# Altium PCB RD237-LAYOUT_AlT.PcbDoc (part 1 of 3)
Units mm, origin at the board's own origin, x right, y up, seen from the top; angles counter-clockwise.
Board outline 100 x 82 mm, 4 copper layers (Top Layer, GND2, POWER 3, Bottom Layer), stack 1.444 mm thick; 308 components, 134 nets, 738 pads, 304 vias.
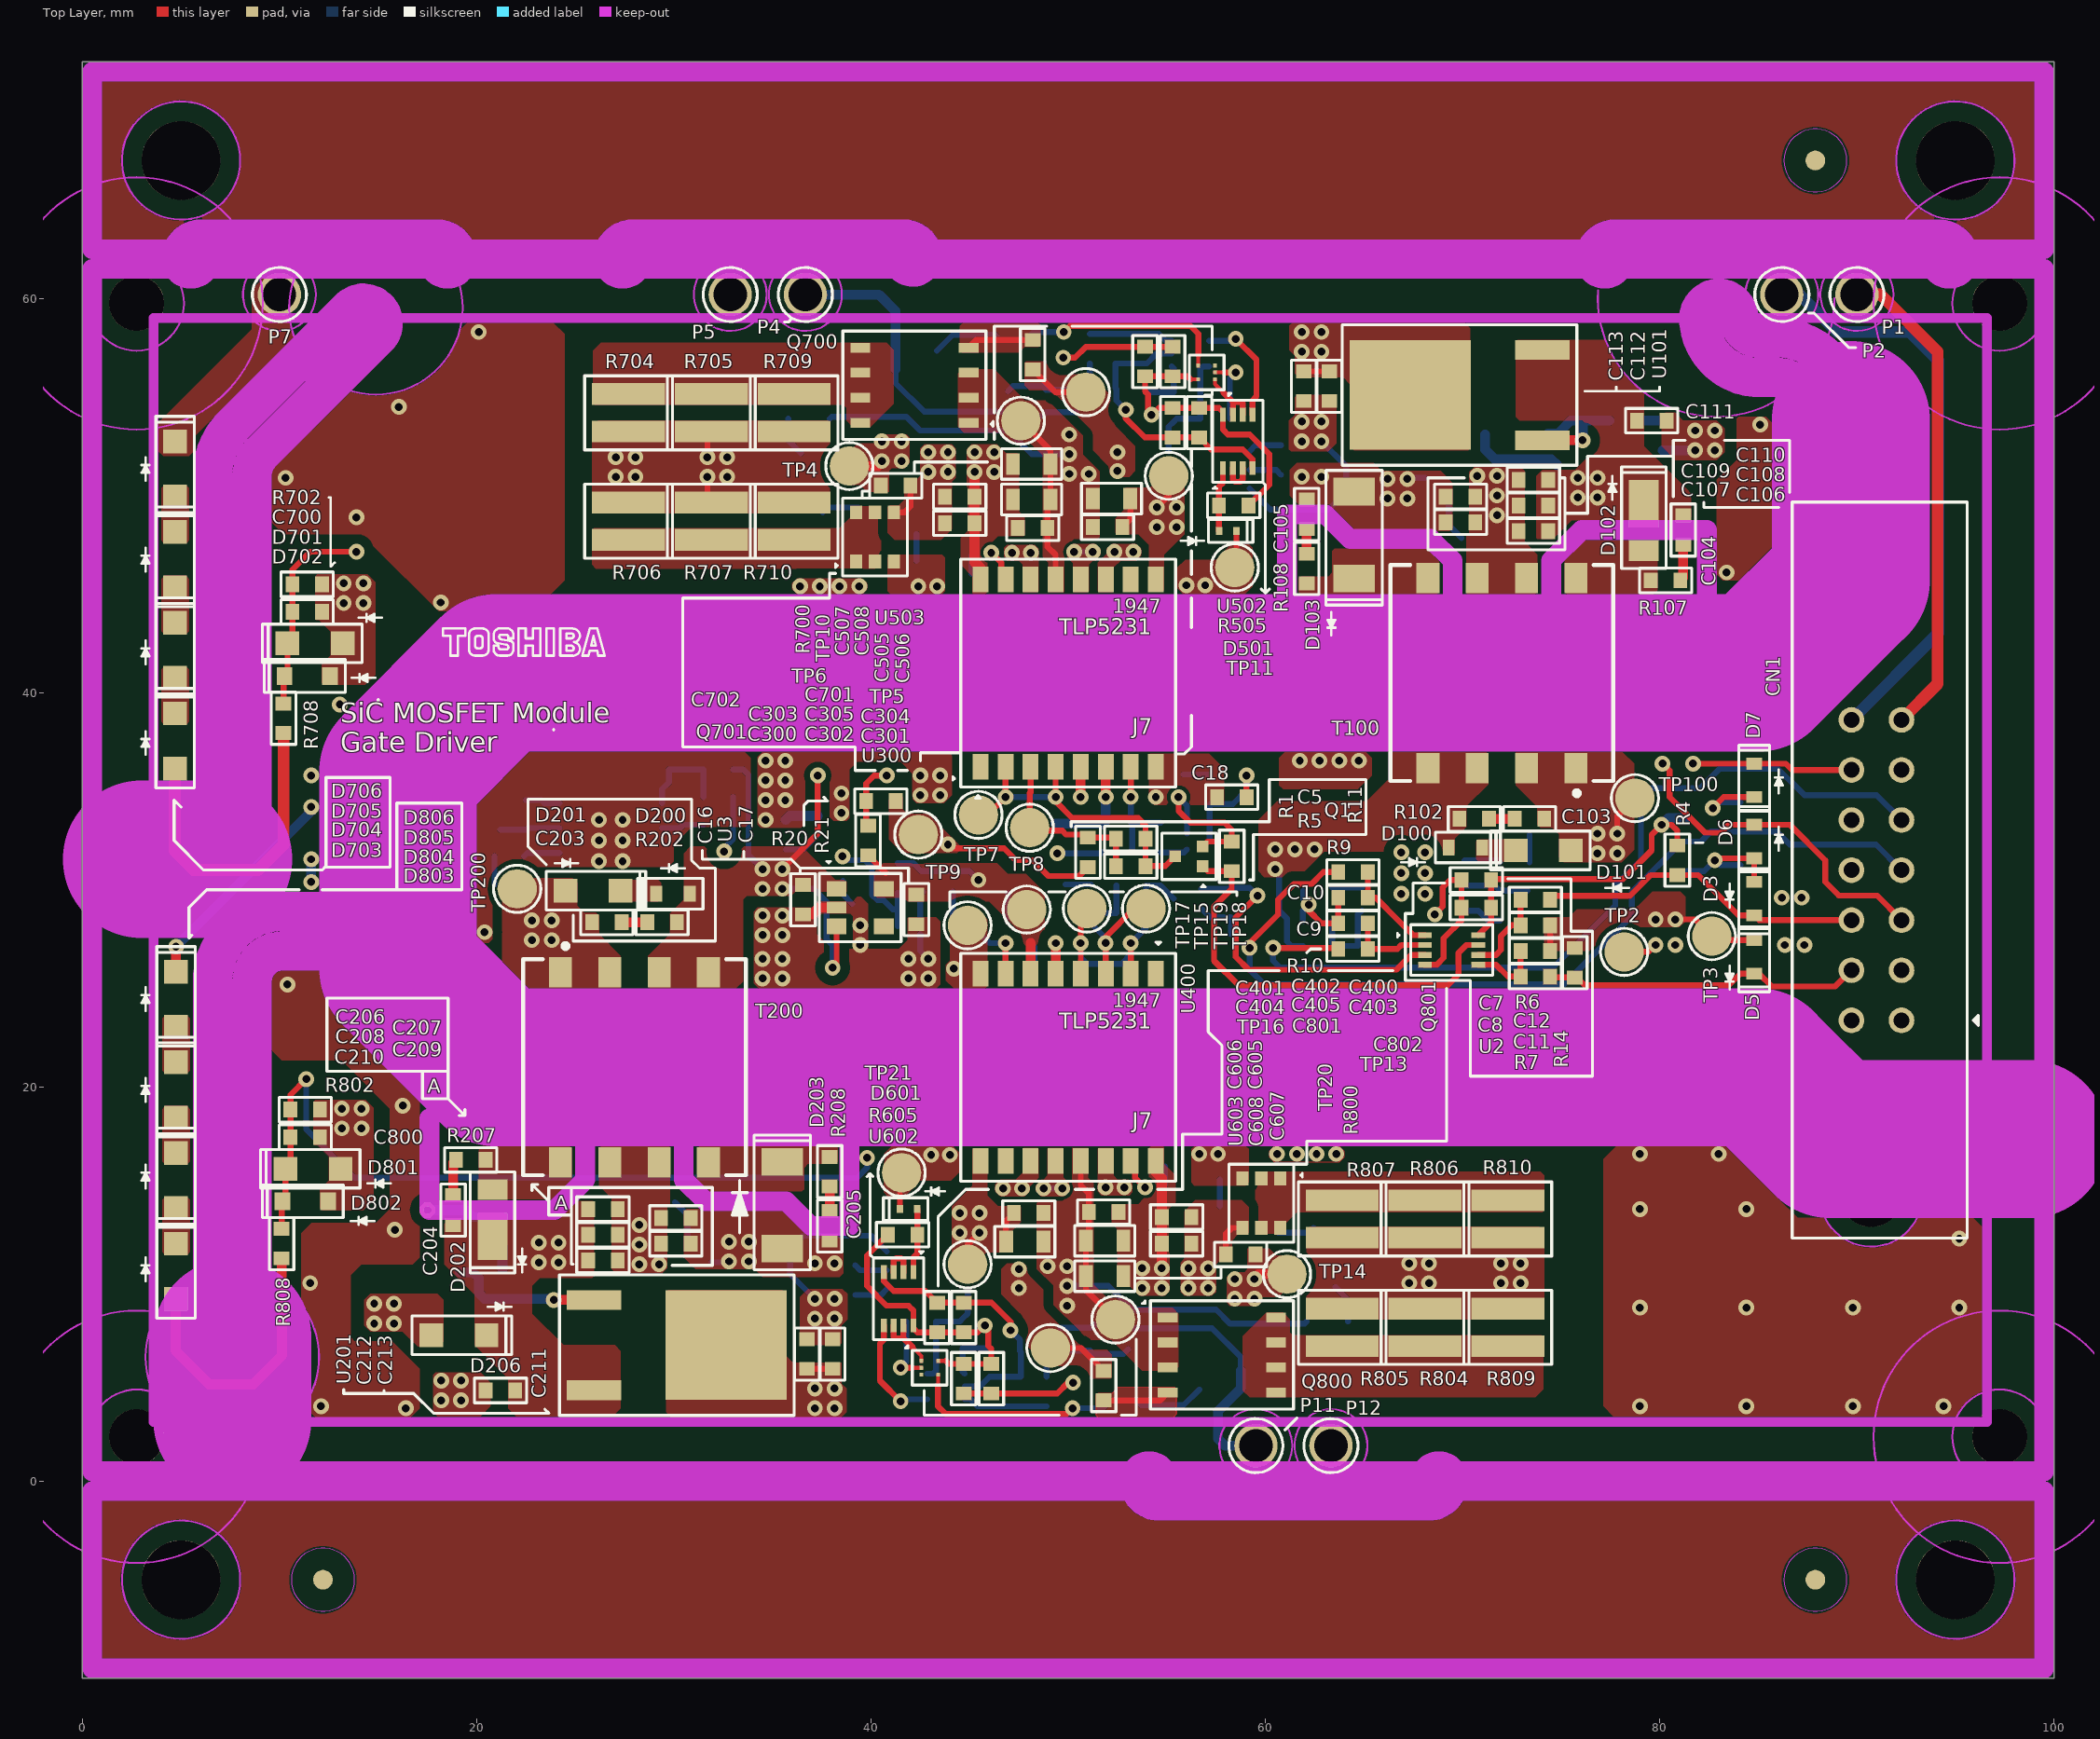
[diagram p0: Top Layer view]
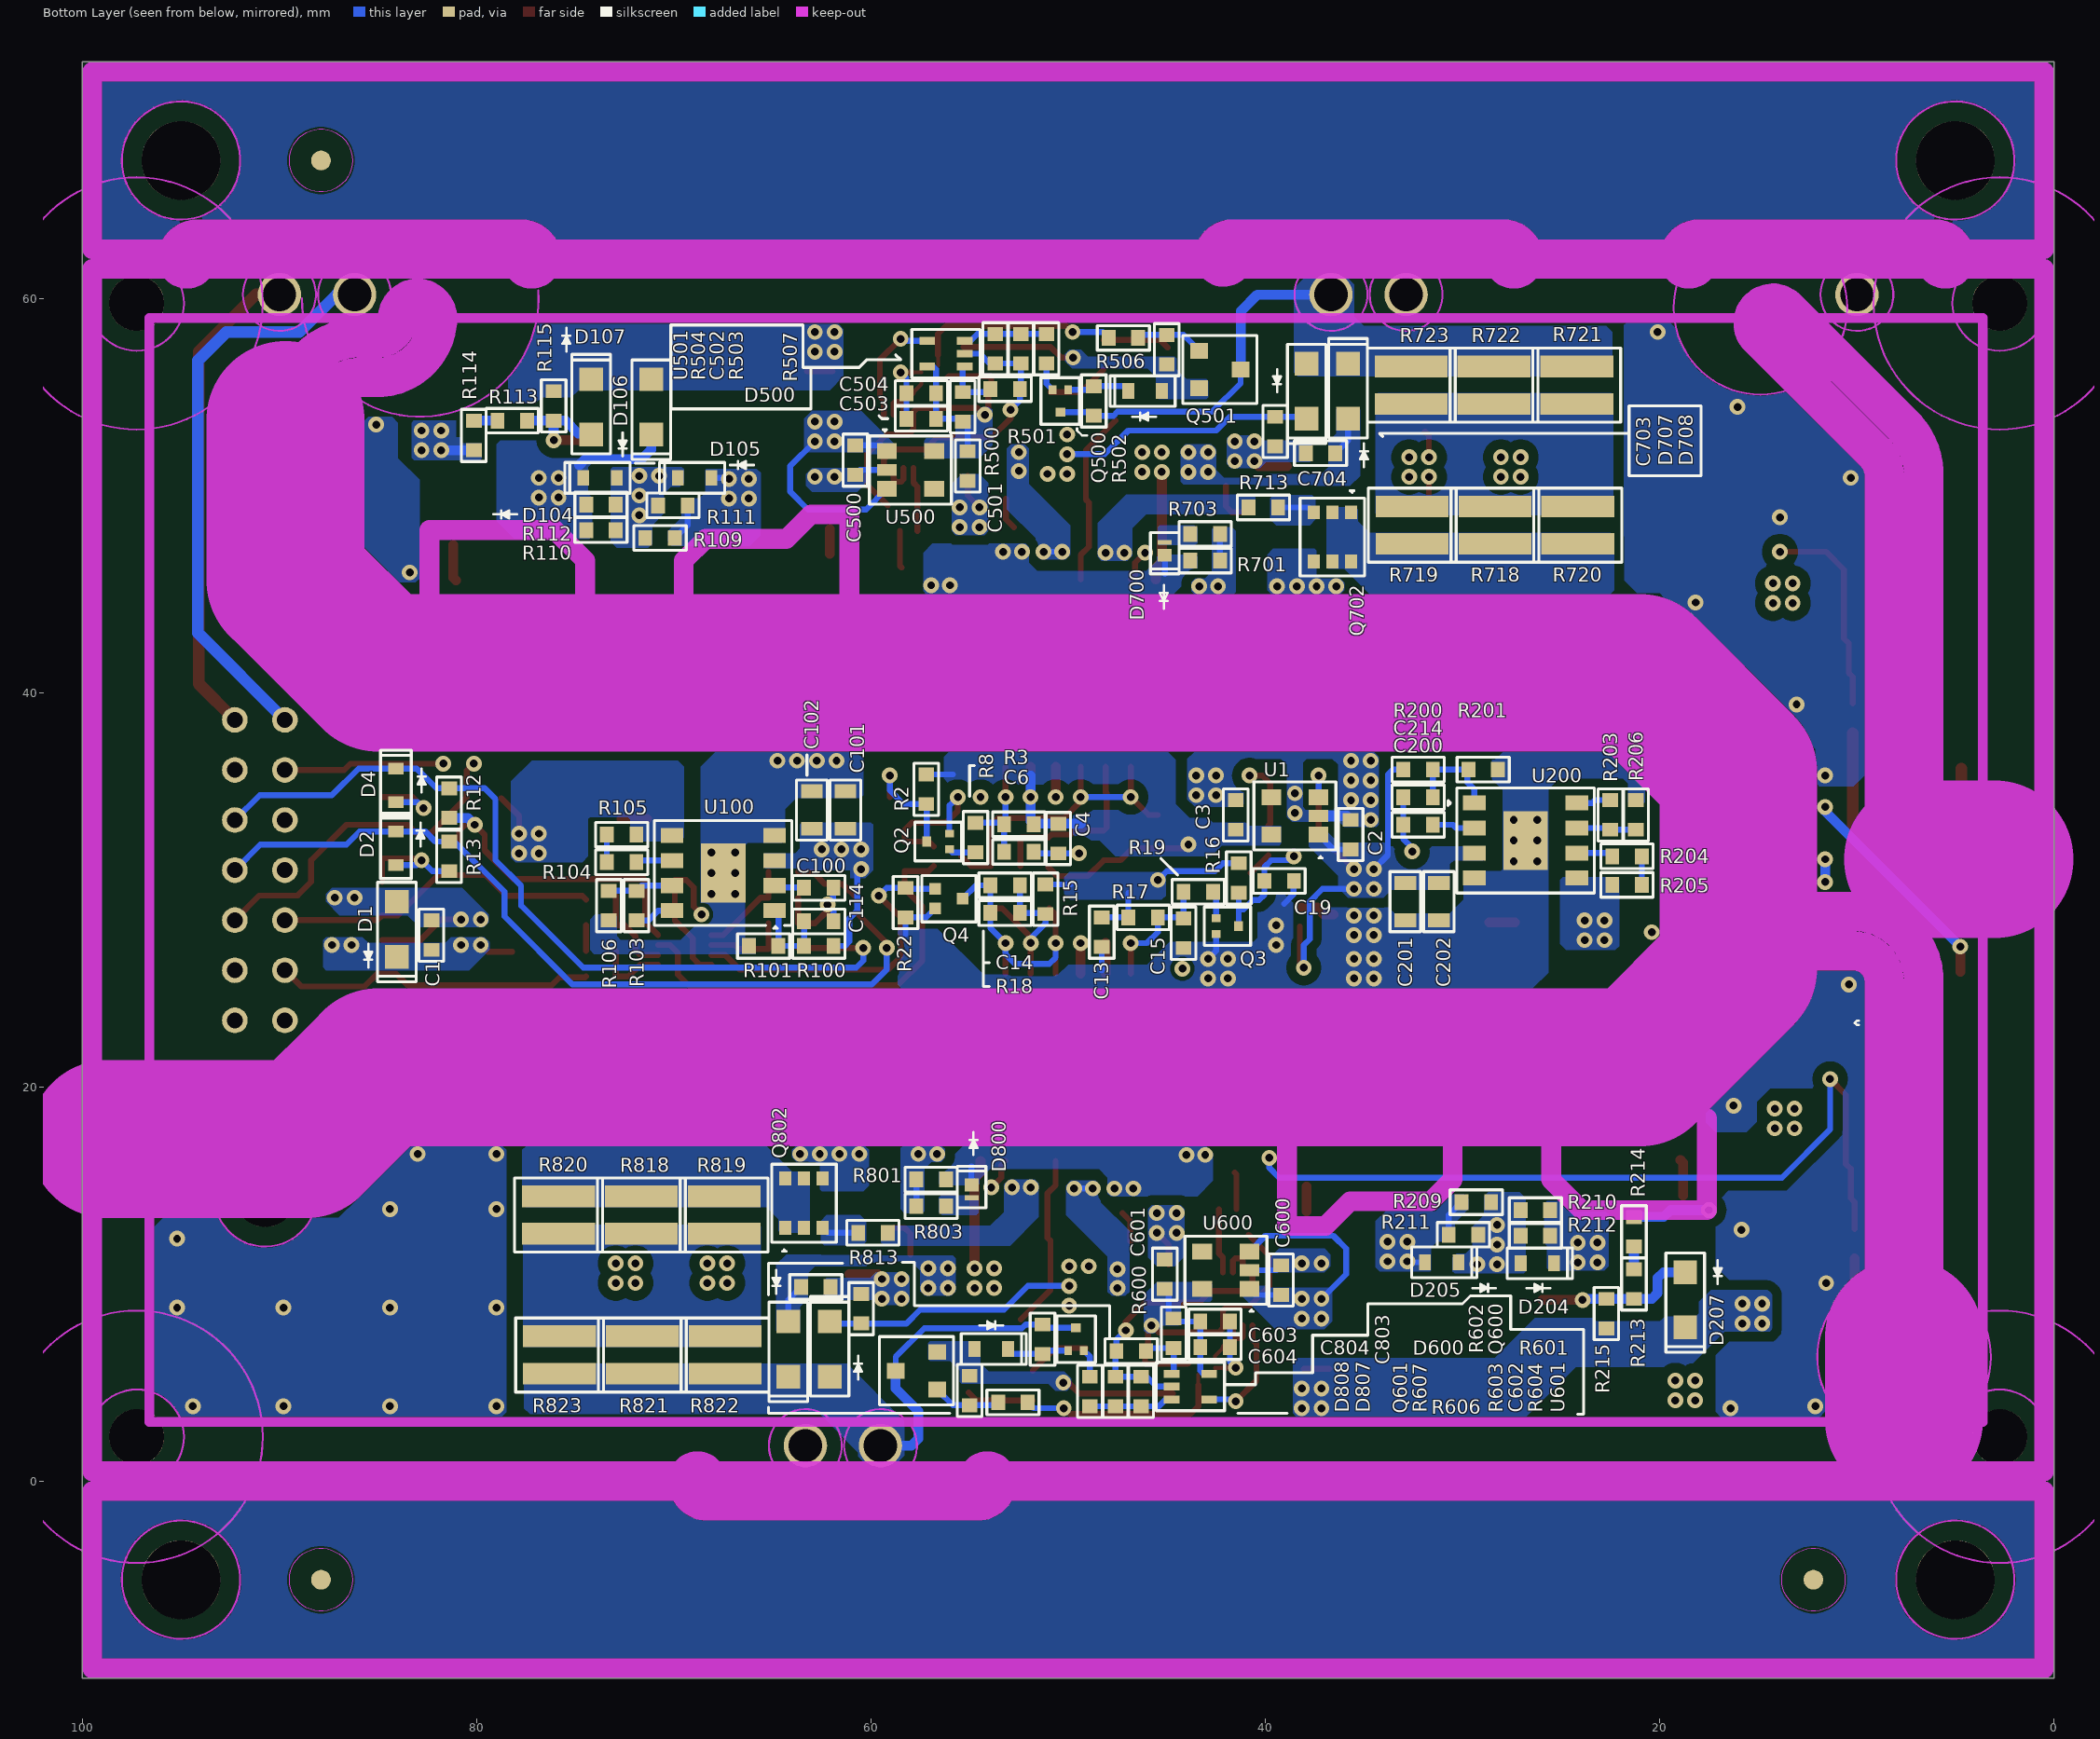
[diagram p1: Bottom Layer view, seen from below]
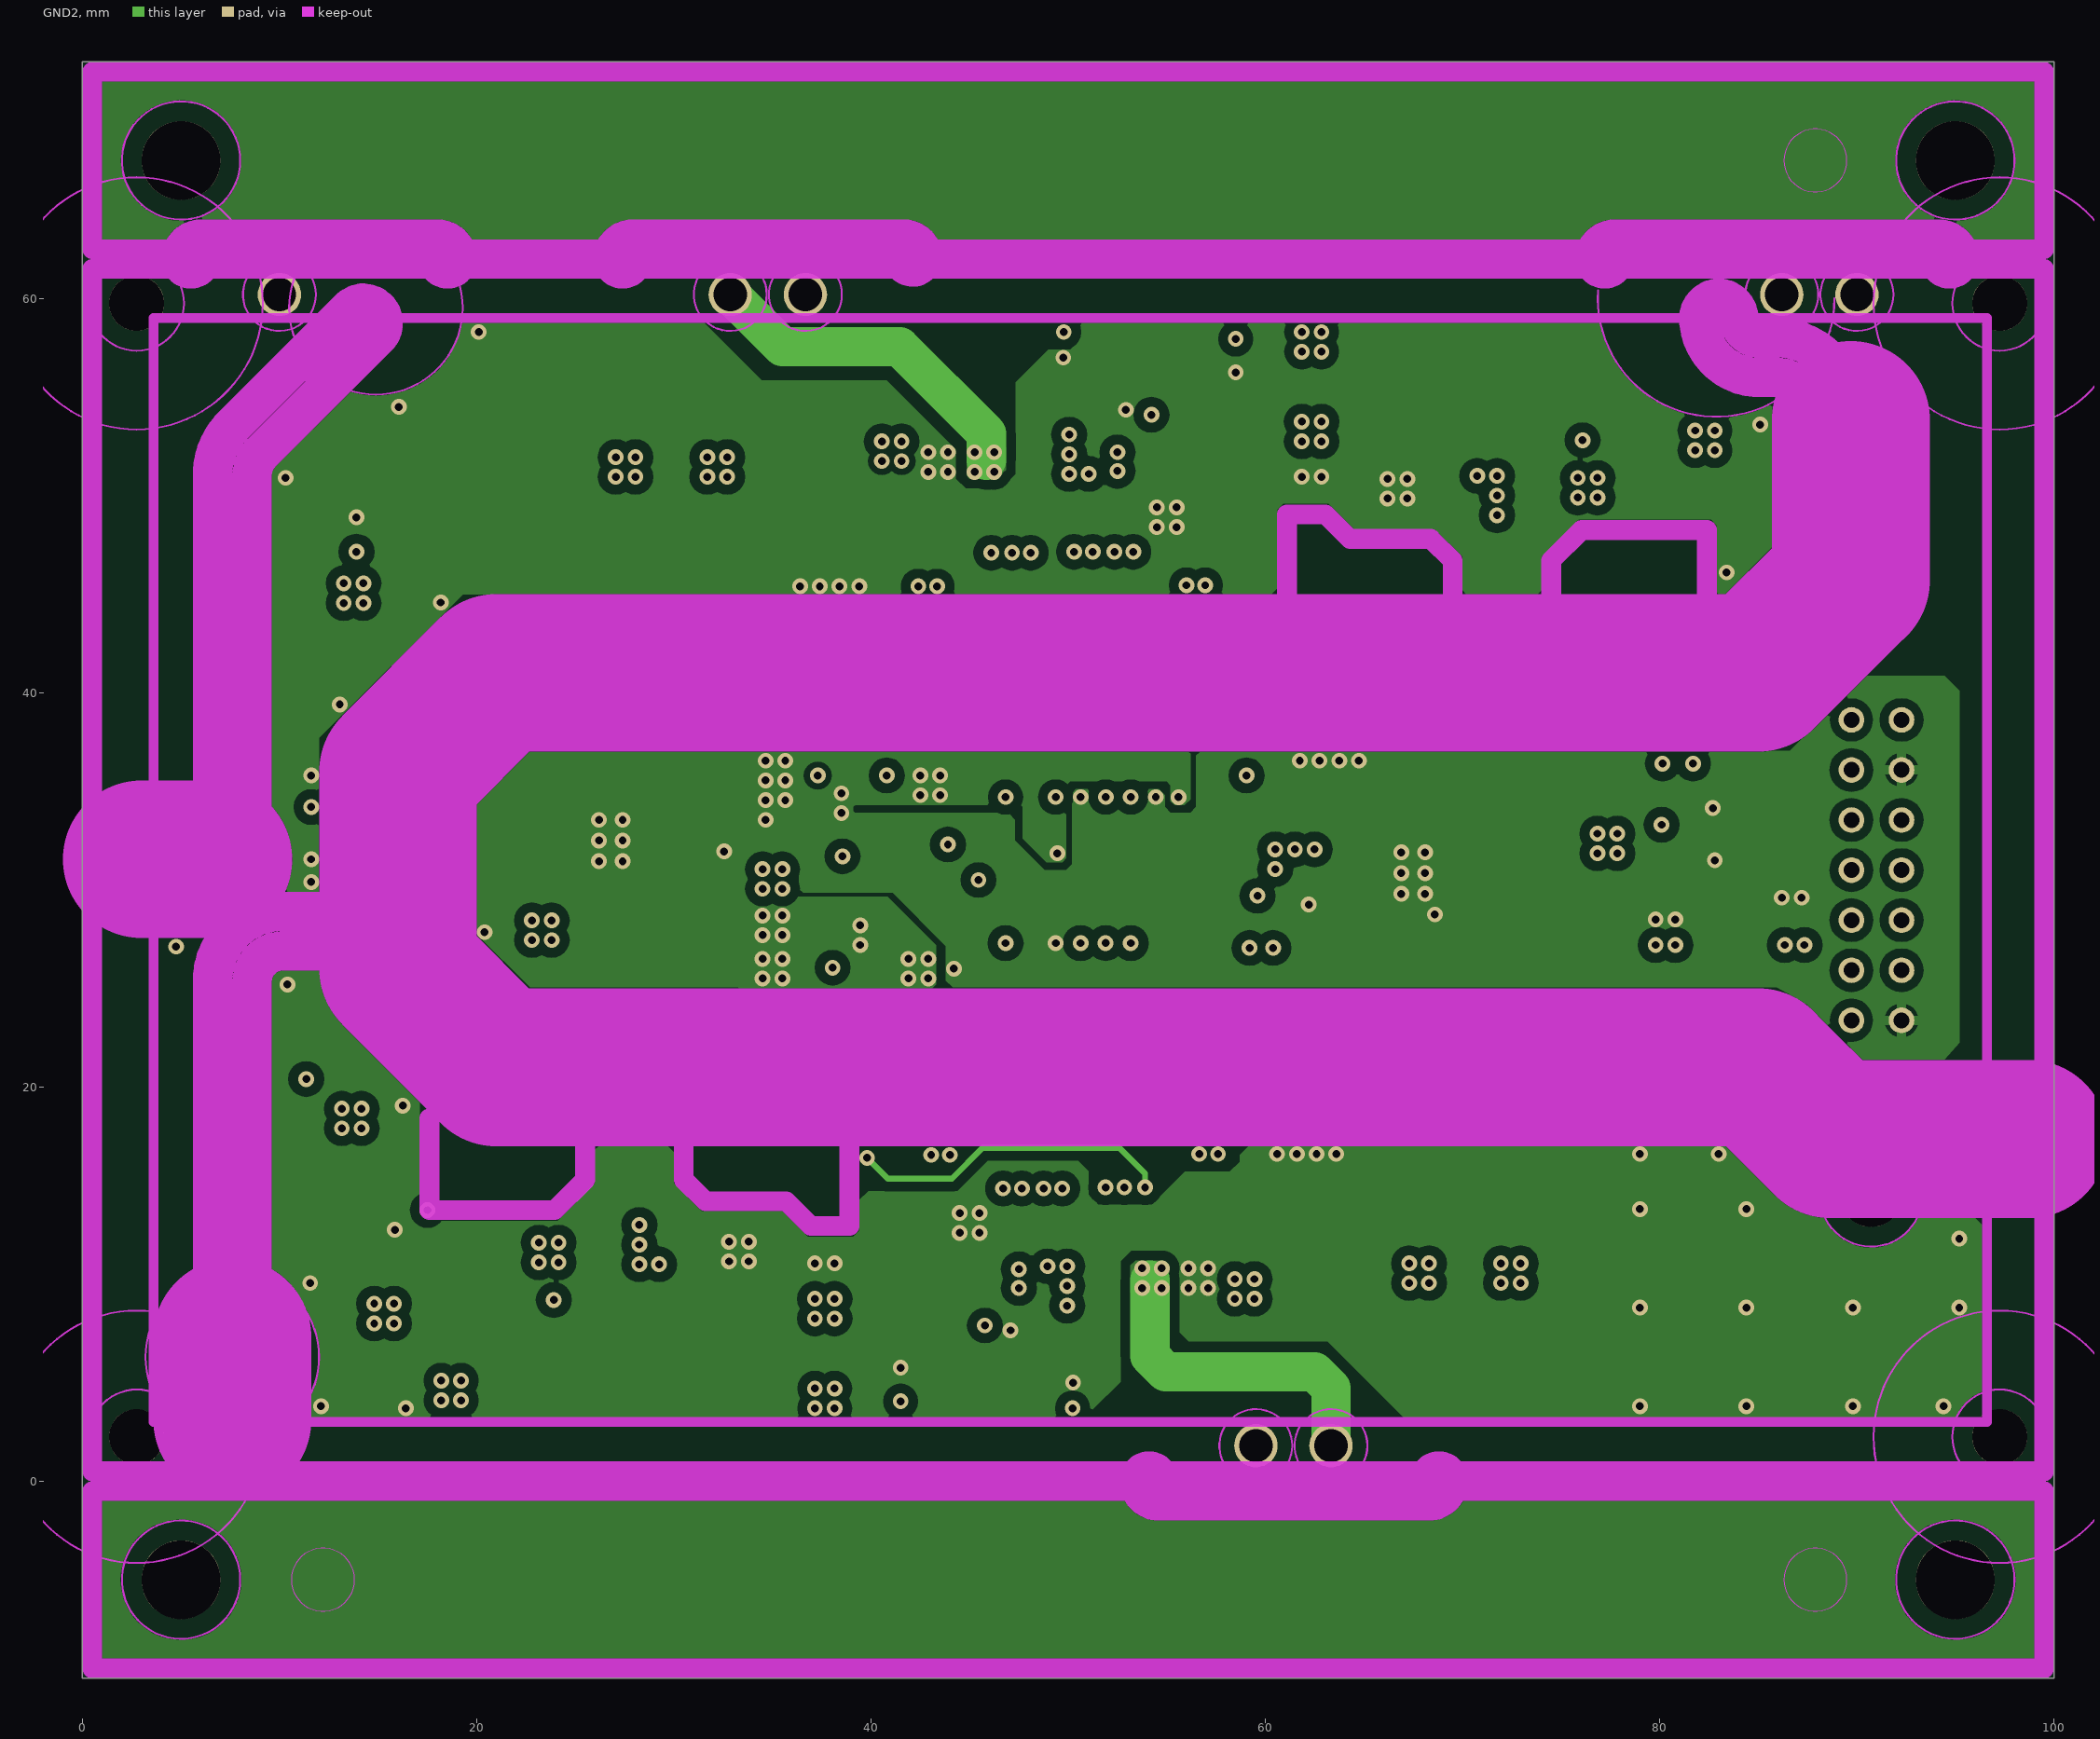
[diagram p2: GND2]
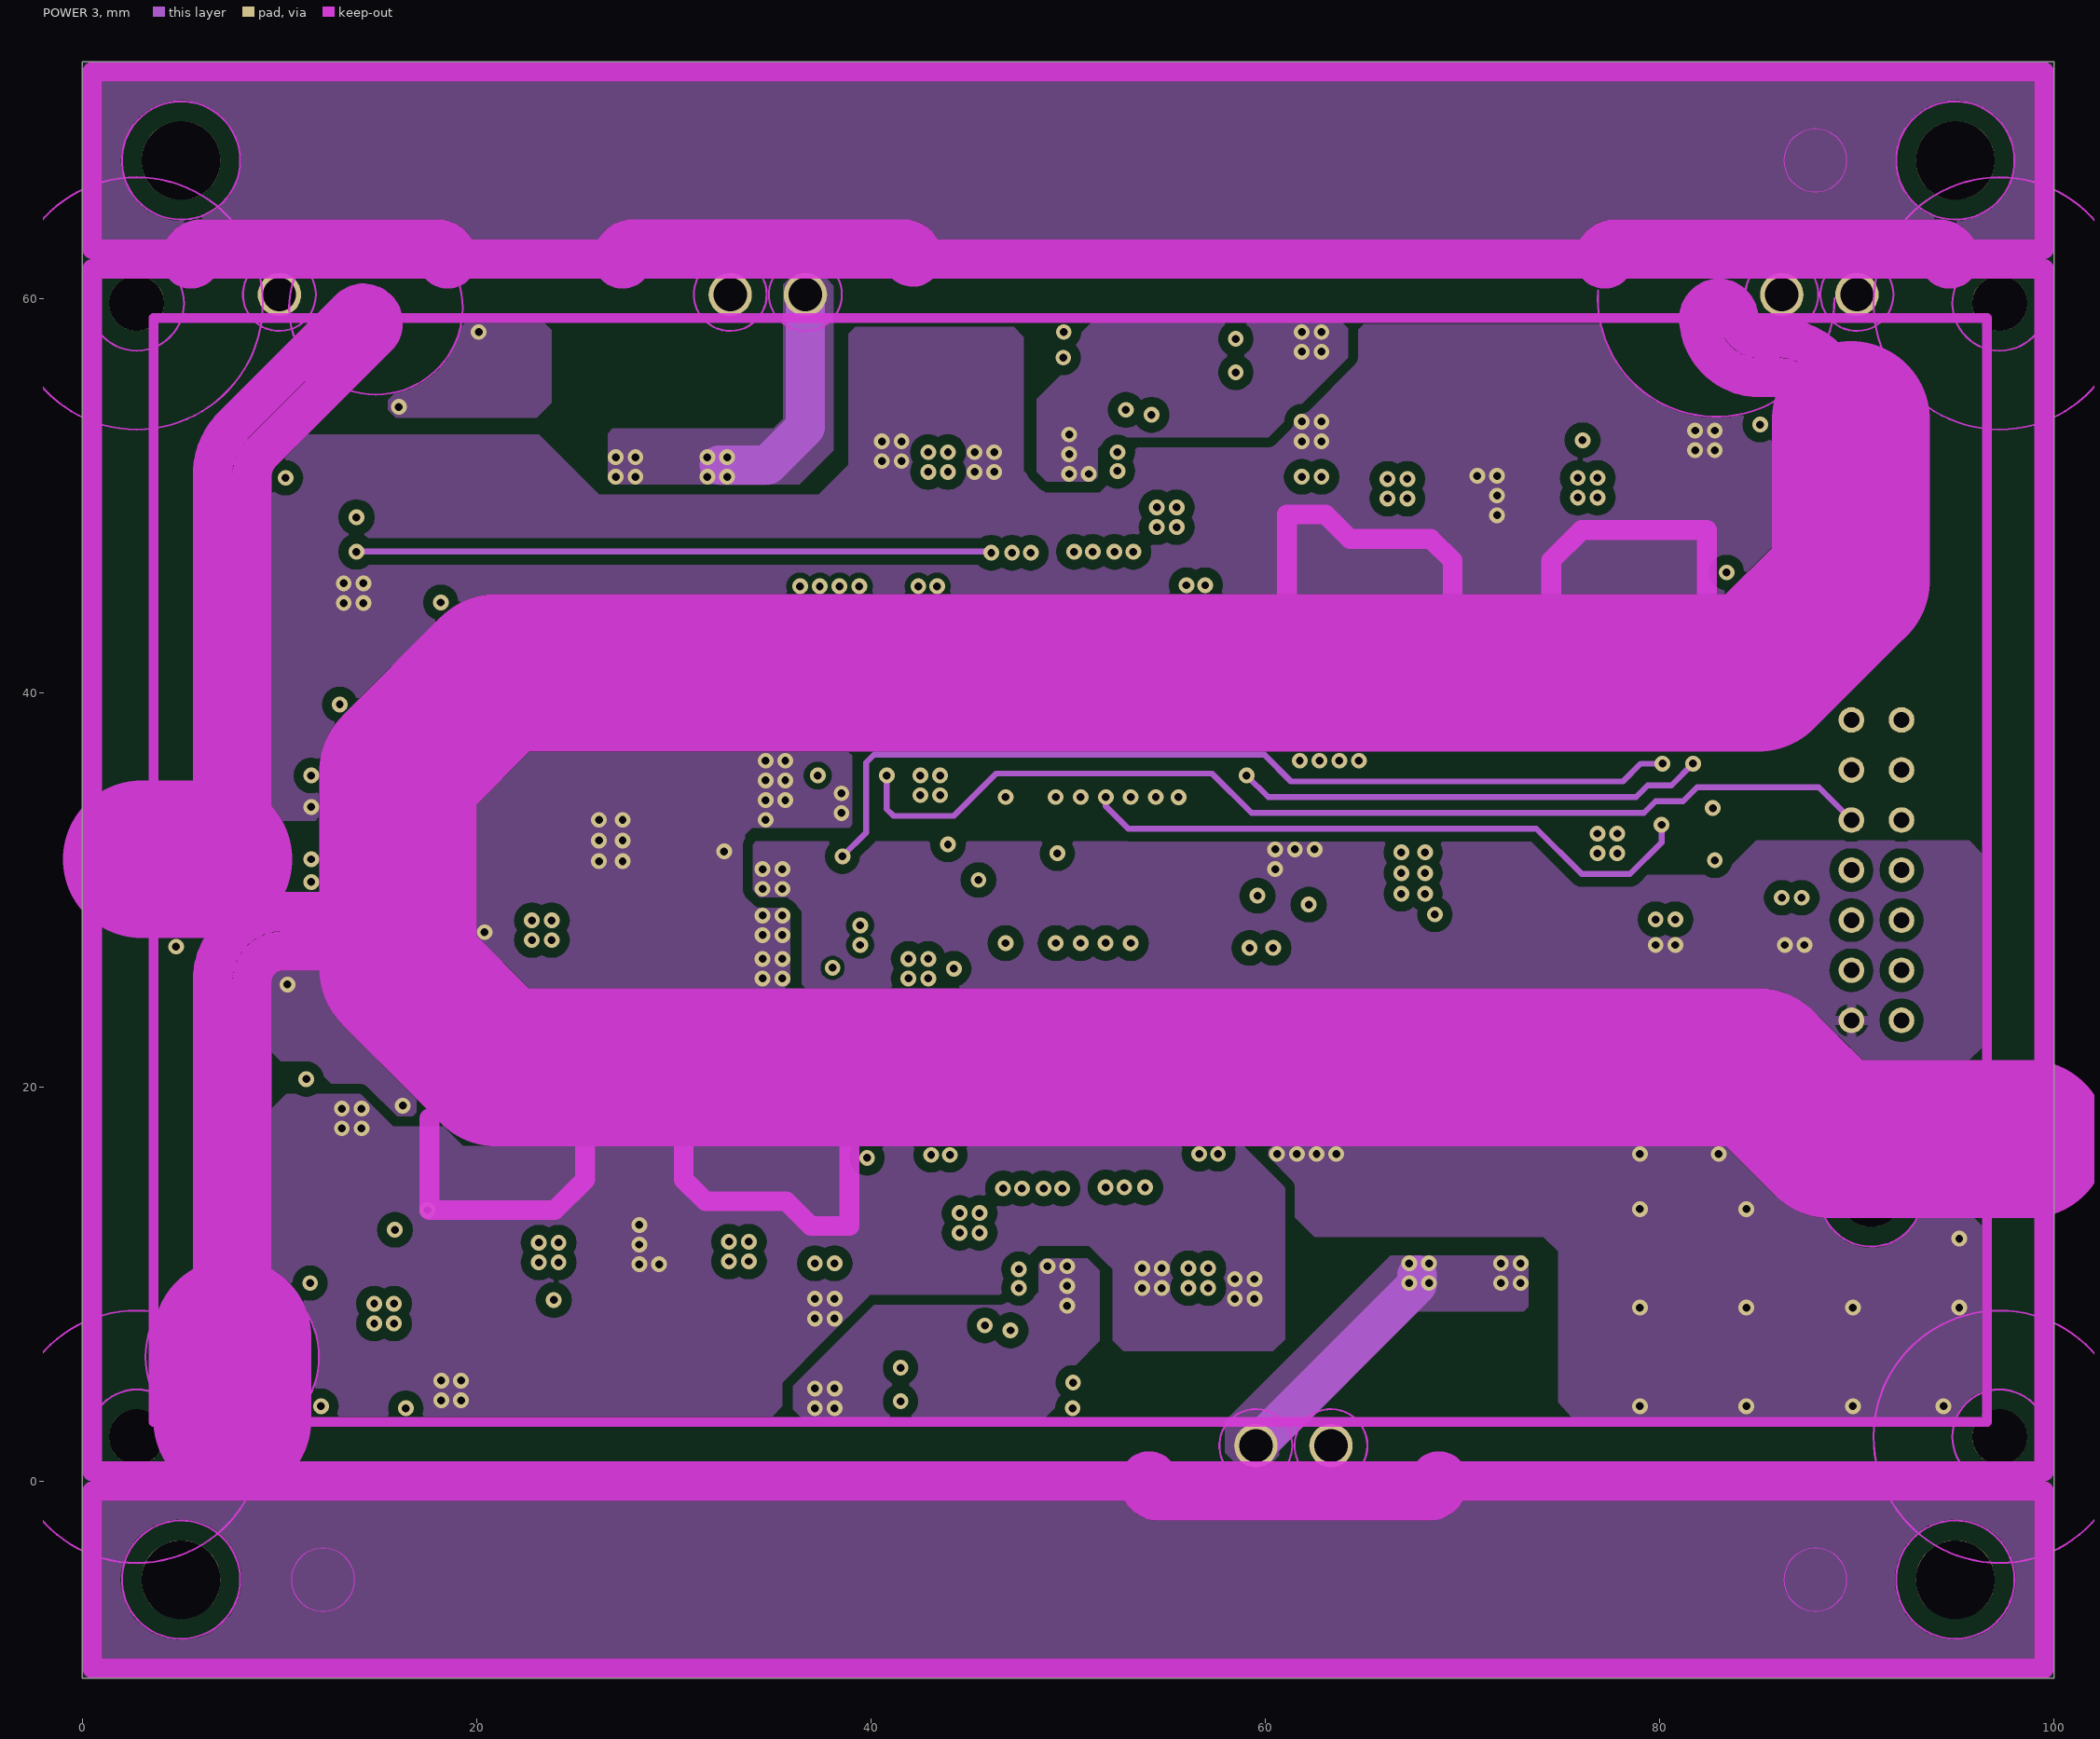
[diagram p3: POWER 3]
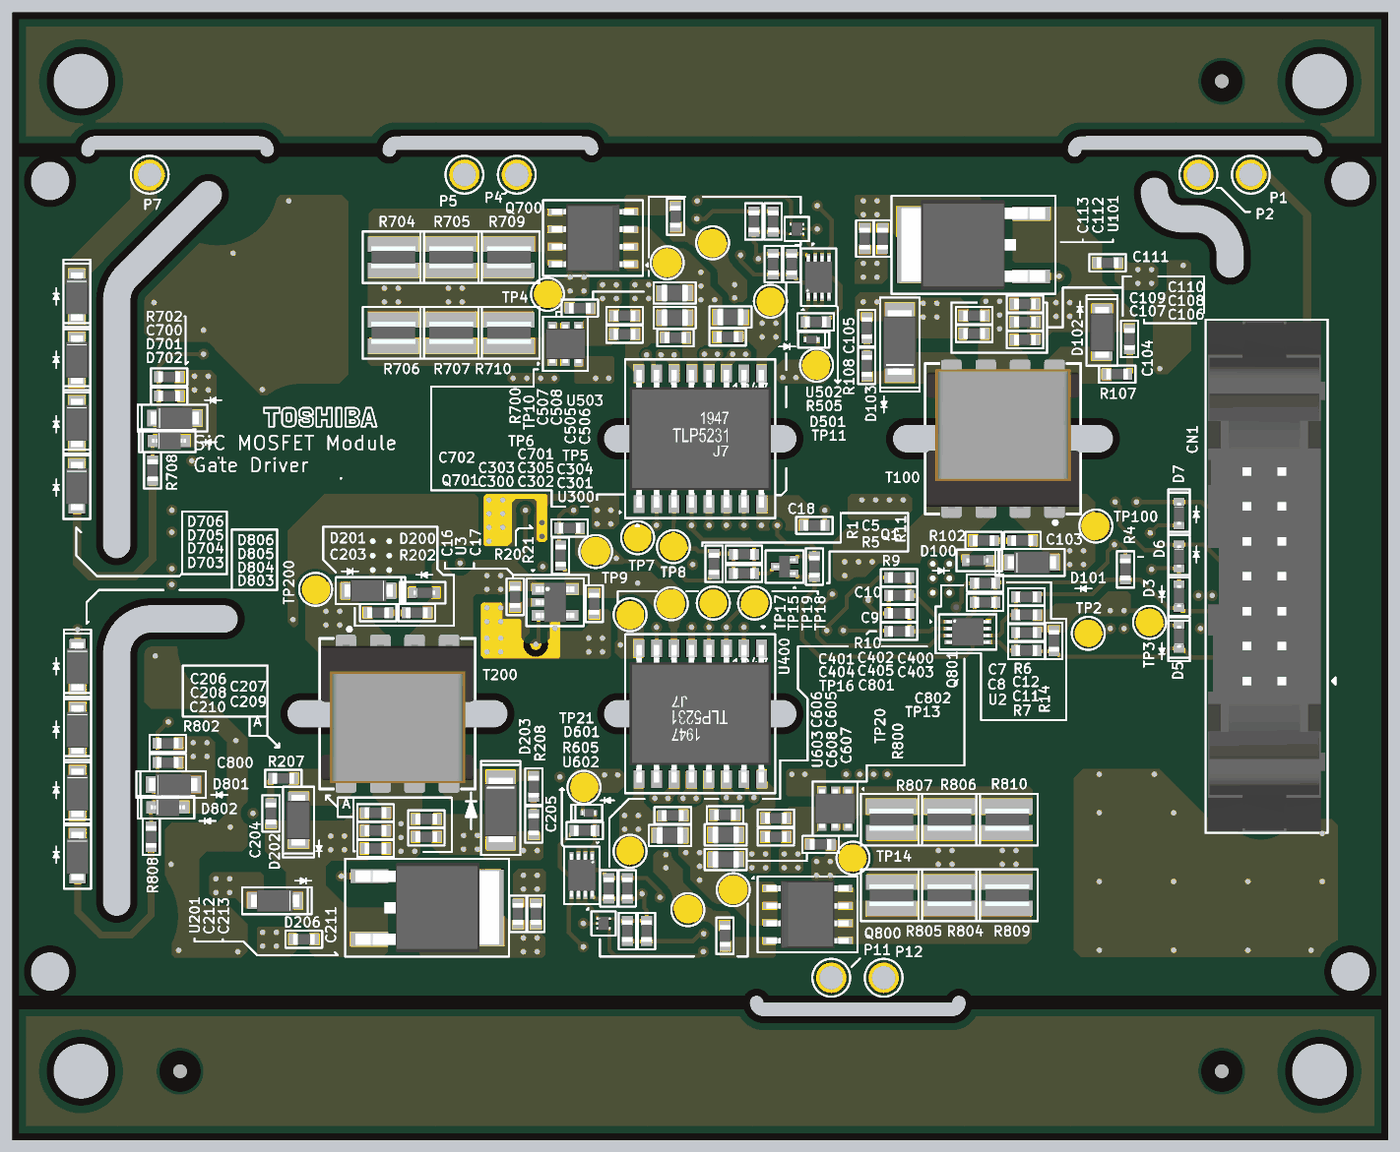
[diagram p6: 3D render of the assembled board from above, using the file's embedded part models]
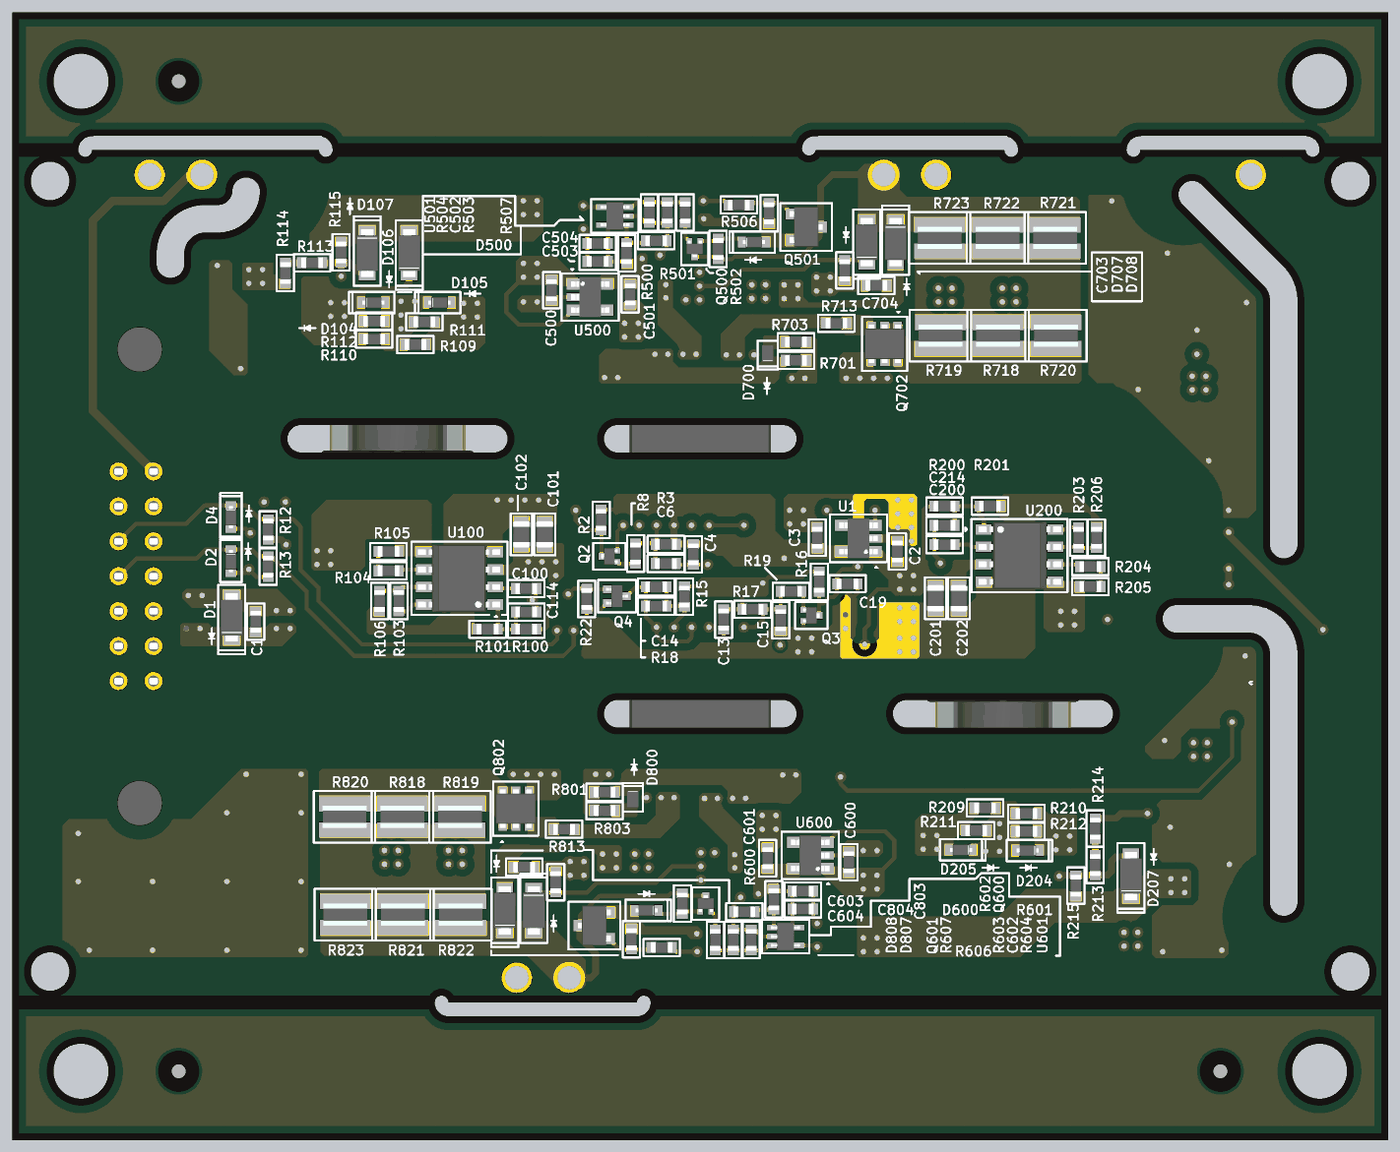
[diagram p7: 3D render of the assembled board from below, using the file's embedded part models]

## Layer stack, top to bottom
Top Solder: solder mask 0.018, Solder Resist, Dk 3.5
Top Layer: signal copper 0.018
Dielectric 1: dielectric 0.12, FR-4, Dk 4.8
GND2: signal copper 0.035
Dielectric 3: prepreg 0.609, FR-4, Dk 4.1
POWER 3: signal copper 0.035
Dielectric 2: prepreg 0.609, FR-4, Dk 4.1
Bottom Layer: signal copper 0.018
Bottom Solder: solder mask 0.018, Solder Resist, Dk 3.5

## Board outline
0,-10 0,72 100,72 100,-10
cut-out: 21,20 cw(c21,21) 21,22 35,22 cw(c35,21) 36,21 cw(c35,21) 35,20
cut-out: 65,40 cw(c65,41) 65,42 79,42 cw(c79,41) 80,41 cw(c79,41) 79,40
cut-out: 82,59 ccw(c85.05,59.05) 85.05,56 85.96,56 cw(c85.96,54.46) 87.5,54.46 87.5,53.7 ccw(c88.5,53.7) 89.5,53.7 89.5,54.46 ccw(c85.96,54.46) 85.96,58 85.05,58 cw(c85.05,59.05) 84.002,59 ccw(c83.001,59)
cut-out: 44,40 cw(c44,41) 44,42 56,42 cw(c56,41) 57,41 cw(c56,41) 56,40
cut-out: 44,20 cw(c44,21) 44,22 56,22 cw(c56,21) 57,21 cw(c56,21) 56,20
cut-out: 6.6,33.3 6.6,51.048 cw(c10.14,51.048) 7.637,53.552 13.543,59.457 cw(c14.25,58.75) 15.25,58.75 cw(c14.25,58.75) 14.957,58.043 9.052,52.137 ccw(c10.14,51.048) 8.601,51.048 8.601,33.3 cw(c7.6,33.3)
cut-out: 6.6,7.3 6.6,25.36 cw(c10.14,25.36) 10.14,28.9 11.8,28.9 cw(c11.8,27.9) 12.8,27.9 cw(c11.8,27.9) 11.8,26.9 10.14,26.9 ccw(c10.14,25.36) 8.6,25.36 8.6,7.3 cw(c7.6,7.3)
cut-out: 76.712,62 ccw(c77.212,62) 77.712,62 94.2,62 ccw(c94.7,62) 95.2,62 ccw(c94.2,62) 94.2,63 77.712,63 ccw(c77.712,62)
cut-out: 5,62 ccw(c5.5,62) 6,62 18.021,62 ccw(c18.521,62) 19.022,62 ccw(c18.021,62) 18.021,63 6,63 ccw(c6,62)
cut-out: 26.9,62 ccw(c27.4,62) 27.9,61.996 41.61,61.996 ccw(c42.1,62.1) 42.6,62.1 ccw(c41.703,62.1) 41.703,62.997 27.897,62.997 ccw(c27.897,62)
cut-out: 54.6,-1 68.3,-1 ccw(c68.3,0) 69.3,0 ccw(c68.8,0) 68.3,0 54.6,0 ccw(c54.1,0) 53.6,0 ccw(c54.6,0)
cut-out: 11.532,26.9 cw(c11.532,27.9) 11.532,28.9 15.4,28.9 cw(c15.4,27.9) 16.4,27.9 cw(c15.4,27.9) 15.4,26.9

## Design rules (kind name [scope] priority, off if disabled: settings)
Clearance polygon [All vs OnLayer('Keep-Out Layer')] p1: gap=0.001 ignorepadtopadclearanceinfootprint=TRUE
Clearance Clearance_PIN_1 [WithinRoom('Room-U400')] p2: gap=0.15 ignorepadtopadclearanceinfootprint=TRUE
Clearance Clearance_PIN [WithinRoom('Room-U300')] p3: gap=0.15 ignorepadtopadclearanceinfootprint=TRUE
Clearance Clearance_D26H [WithinRoom('Room-D26H')] p4: gap=0.5 ignorepadtopadclearanceinfootprint=TRUE except(0.15: Track-SMDPad SMDPad-Poly; 0.2: SMDPad-Via; 0.3: Via-Poly; 0.45: Track-Poly Via-Via)
Clearance Clearance_u1 [WithinRoom('Room-u1')] p5: gap=0.5 ignorepadtopadclearanceinfootprint=TRUE except(0.15: Track-SMDPad SMDPad-Poly; 0.2: SMDPad-Via; 0.3: Via-Poly; 0.45: Track-Poly Via-Via)
Clearance Clearance_Q2 [WithinRoom('Room-Q2')] p6: gap=0.5 ignorepadtopadclearanceinfootprint=TRUE except(0.15: Track-SMDPad SMDPad-Poly; 0.2: SMDPad-Via; 0.3: Via-Poly; 0.45: Track-Poly Via-Via)
Clearance Clearance_Q3 [WithinRoom('Room-Q3')] p7: gap=0.5 ignorepadtopadclearanceinfootprint=TRUE except(0.15: Track-SMDPad SMDPad-Poly; 0.2: SMDPad-Via; 0.3: Via-Poly; 0.45: Track-Poly Via-Via)
Clearance Clearance_Q8H [WithinRoom('Room-Q8H')] p8: gap=0.5 ignorepadtopadclearanceinfootprint=TRUE except(0.15: Track-SMDPad SMDPad-Poly; 0.2: SMDPad-Via; 0.3: Via-Poly; 0.45: Track-Poly Via-Via)
Clearance Clearance_D26I [WithinRoom('Room-D26I')] p9: gap=0.5 ignorepadtopadclearanceinfootprint=TRUE except(0.15: Track-SMDPad SMDPad-Poly; 0.2: SMDPad-Via; 0.3: Via-Poly; 0.45: Track-Poly Via-Via)
Clearance Clearance_U10G [WithinRoom('Room-U10G')] p10: gap=0.5 ignorepadtopadclearanceinfootprint=TRUE except(0.075: SMDPad-SMDPad; 0.15: Track-Track Track-SMDPad SMDPad-Poly; 0.45: Track-Poly Via-Via)
Clearance Clearance_Q9H [WithinRoom('Room-Q9H')] p11: gap=0.5 ignorepadtopadclearanceinfootprint=TRUE except(0.075: SMDPad-SMDPad; 0.15: Track-Track Track-SMDPad SMDPad-Poly; 0.45: Track-Poly Via-Via)
Clearance Clearance_Q9I [WithinRoom('Room-q9i')] p12: gap=0.5 ignorepadtopadclearanceinfootprint=TRUE except(0.075: SMDPad-SMDPad; 0.15: Track-Track Track-SMDPad SMDPad-Poly; 0.45: Track-Poly Via-Via)
Clearance Clearance_Q8i [WithinRoom('Room-q8i')] p13: gap=0.5 ignorepadtopadclearanceinfootprint=TRUE except(0.075: SMDPad-SMDPad; 0.15: Track-Track Track-SMDPad SMDPad-Poly; 0.45: Track-Poly Via-Via)
Clearance Clearance_U9G [WithinRoom('Room-U9G')] p14: gap=0.5 ignorepadtopadclearanceinfootprint=TRUE except(0.075: SMDPad-SMDPad; 0.15: Track-Track Track-SMDPad SMDPad-Poly; 0.45: Track-Poly Via-Via)
Clearance Clearance_U8F [WithinRoom('Room-U8F')] p15: gap=0.5 ignorepadtopadclearanceinfootprint=TRUE except(0.075: SMDPad-SMDPad; 0.15: Track-Track Track-SMDPad SMDPad-Poly; 0.45: Track-Poly Via-Via)
Clearance Clearance_U8F_1 [WithinRoom('Room-Q5G')] p16: gap=0.5 ignorepadtopadclearanceinfootprint=TRUE except(0.075: SMDPad-SMDPad; 0.15: Track-Track Track-SMDPad SMDPad-Poly; 0.45: Track-Poly Via-Via)
Clearance Clearance_U2 [WithinRoom('Room-U2')] p17: gap=0.5 ignorepadtopadclearanceinfootprint=TRUE except(0.075: SMDPad-SMDPad; 0.15: Track-Track Track-SMDPad SMDPad-Poly; 0.45: Track-Poly Via-Via)
Clearance Clearance_U8G [WithinRoom('Room-U8G')] p18: gap=0.5 ignorepadtopadclearanceinfootprint=TRUE except(0.075: SMDPad-SMDPad; 0.15: Track-Track Track-SMDPad SMDPad-Poly; 0.45: Track-Poly Via-Via)
Clearance Clearance_U9F [WithinRoom('Room-U9F')] p19: gap=0.5 ignorepadtopadclearanceinfootprint=TRUE except(0.075: SMDPad-SMDPad; 0.15: Track-Track Track-SMDPad SMDPad-Poly; 0.45: Track-Poly Via-Via)
Clearance Clearance_U10F [WithinRoom('Room-U10F')] p20: gap=0.5 ignorepadtopadclearanceinfootprint=TRUE except(0.075: SMDPad-SMDPad; 0.15: Track-Track Track-SMDPad SMDPad-Poly; 0.45: Track-Poly Via-Via)
Clearance Clearance_u3 [WithinRoom('Room-u3')] p21: gap=0.5 ignorepadtopadclearanceinfootprint=TRUE except(0.15: Track-SMDPad SMDPad-Poly; 0.25: SMDPad-Via; 0.3: Via-Poly; 0.45: Track-Poly Via-Via)
Clearance [All vs (InNetClass('All Nets'))] p22: gap=0.5 ignorepadtopadclearanceinfootprint=TRUE except(0: Arc-Hole Track-Hole SMDPad-Hole THPad-Hole Via-Hole Fill-Poly Fill-Hole Poly-Hole Region-Hole Text-Hole; 0.1: Poly-Text; 0.25: SMDPad-Fill SMDPad-Region SMDPad-Text; 0.254: THPad-Region THPad-Text Region-Region Region-Text Text-Text; 0.45: Track-THPad Track-Region Track-Text THPad-Fill THPad-Poly Via-Via Via-Fill Via-Region Via-Text Fill-Fill Fill-Region Fill-Text Poly-Region)
Height Height_1 [InComponentClass('Bottom Side Components')] p1: minheight=0 maxheight=2.5 prefheight=2.5
Height [All] p2: minheight=0 maxheight=50 prefheight=12.7
HoleSize [IsVia] p1: absolutevalues=TRUE maxlimit=0.4 minlimit=0.4 maxpercent=80.000 minpercent=20.000
MinimumSolderMaskSliver [All] p1: minsoldermaskwidth=0.1
PolygonConnect PolygonConnect_g [IsVia] p1: connectstyle=Direct reliefconductorwidth=0.254 reliefentries=4 polygonreliefangle="90 Angle" airgapwidth=0.254
PolygonConnect PolygonConnect_H [HasFootprint('XG4A-1431')] p2: connectstyle=Relief reliefconductorwidth=0.5 reliefentries=4 polygonreliefangle="90 Angle" airgapwidth=0.2
PolygonConnect [All] p3: connectstyle=Direct reliefconductorwidth=0.254 reliefentries=4 polygonreliefangle="90 Angle" airgapwidth=0.254
RoomDefinition Room-U400 [False] p1: confinementstyle=ConfineIn formatcopy=TRUE lockcomponents=FALSE outline 56.3,14.3 44.95,14.3 44.95,17.05 56.3,17.05
RoomDefinition Room-U300 [False] p2: confinementstyle=ConfineIn formatcopy=TRUE lockcomponents=FALSE outline 43.7,47.7 55.05,47.7 55.05,44.95 43.7,44.95
RoomDefinition Room-Q3 [False] p3: confinementstyle=ConfineIn formatcopy=TRUE lockcomponents=FALSE outline 41.925,29.129 43.104,29.129 43.104,27.171 41.925,27.171
RoomDefinition Room-Q2 [False] p4: confinementstyle=ConfineIn formatcopy=TRUE lockcomponents=FALSE outline 55.421,33.175 56.9,33.175 56.9,31.5 55.421,31.5
RoomDefinition Room-U10F [False vs False] p5: confinementstyle=ConfineIn formatcopy=TRUE lockcomponents=FALSE outline 50.271,56.179 52.029,56.179 52.029,54.421 50.271,54.421
RoomDefinition Room-U8F [False vs False] p6: confinementstyle=ConfineIn formatcopy=TRUE lockcomponents=FALSE outline 53.45,58.775 55.525,58.775 55.525,55.825 53.45,55.825
RoomDefinition Room-D26H [False vs False] p7: confinementstyle=ConfineIn formatcopy=TRUE lockcomponents=FALSE outline 35.05,49.95 46.35,49.95 46.35,44.85 35.05,44.85
RoomDefinition Room-Q8H [False vs False] p8: confinementstyle=ConfineIn formatcopy=TRUE lockcomponents=FALSE outline 39.25,52.15 45.861,52.15 45.861,45.05 39.25,45.05
RoomDefinition Room-Q5G [False] p9: confinementstyle=ConfineIn formatcopy=TRUE lockcomponents=FALSE outline 48.621,7.4 50.579,7.4 50.579,6.221 48.621,6.221
RoomDefinition Room-U8G [False vs False] p10: confinementstyle=ConfineIn formatcopy=TRUE lockcomponents=FALSE outline 44.475,6.175 45.829,6.175 45.829,3.571 44.475,3.571
RoomDefinition Room-q9i [False] p11: confinementstyle=ConfineIn formatcopy=TRUE lockcomponents=FALSE outline 60.421,15.739 64.379,15.739 64.379,12.461 60.421,12.461
RoomDefinition Room-q8i [False] p12: confinementstyle=ConfineIn formatcopy=TRUE lockcomponents=FALSE outline 54.445,17 60.1,17 60.1,12.55 54.445,12.55
RoomDefinition Room-Q9H [False vs False] p13: confinementstyle=ConfineIn formatcopy=TRUE lockcomponents=FALSE outline 18.92,52.02 22.4,52.02 22.4,47 18.92,47
RoomDefinition Room-U2 [False] p14: confinementstyle=ConfineIn formatcopy=TRUE lockcomponents=FALSE outline 66.4,28.45 72.375,28.45 72.375,24.975 66.4,24.975
RoomDefinition Room-U9F [False vs False] p15: confinementstyle=ConfineIn formatcopy=TRUE lockcomponents=FALSE outline 56.471,57.2 60,57.2 60,49.8 56.471,49.8
RoomDefinition Room-U9G [False vs False] p16: confinementstyle=ConfineIn formatcopy=TRUE lockcomponents=FALSE outline 39.7,11.725 43.625,11.725 43.625,5.05 39.7,5.05
RoomDefinition Room-u3 [False] p17: confinementstyle=ConfineIn formatcopy=TRUE lockcomponents=FALSE outline 37.175,30.825 41.675,30.825 41.675,27 37.175,27
RoomDefinition Room-u1 [False vs False] p18: confinementstyle=ConfineIn formatcopy=TRUE lockcomponents=FALSE outline 36.375,36.425 40.6,36.425 40.6,32.25 36.375,32.25
RoutingCorners [All] p1: cornerstyle=45-Degree minsetback=0.05 maxsetback=0.05
RoutingVias [All] p1: holewidth=0.4 width=0.8 viastyle="Through Hole" minholewidth=0.4 minwidth=0.8 maxholewidth=0.4 maxwidth=0.8
SilkToSilkClearance [All] p1: silktosilkclearance=0.1
SilkToSolderMaskClearance [IsPad] p1: minsilkscreentomaskgap=0.1 clearancetoexposedcopper=TRUE
SolderMaskExpansion [All] p1: expansion=0.102 istentingtop=FALSE
Width [All] p1: maxlimit=2 minlimit=0.2 preferedwidth=0.3
24 further rules are at their usual default settings.

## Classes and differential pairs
component class A: C2 C3 C4 C5 C6 C7 C8 C9 C10 C11 C12 C13 C14 C15 C16 C17 C18 C19 D2 D3 D4 D5 D6 D7 Q1 Q2 Q3 Q4 R1 R2 R3 R4 R5 R6 R7 R8 R9 R10 R11 R12 R13 R14 R15 R16 R17 R18 R19 R20 R21 R22 U1 U2 U3
component class B: C100 C101 C102 C103 C104 C105 C106 C107 C108 C109 C110 C111 C112 C113 C114 D100 D101 D102 D103 D104 D105 D106 D107 R100 R101 R102 R103 R104 R105 R106 R107 R108 R109 R110 R111 R112 R113 R114 R115 T100 TP100 U100 U101
component class C: C200 C201 C202 C203 C204 C205 C206 C207 C208 C209 C210 C211 C212 C213 C214 D200 D201 D202 D203 D204 D205 D206 D207 R200 R201 R202 R203 R204 R205 R206 R207 R208 R209 R210 R211 R212 R213 R214 R215 T200 TP200 U200 U201
component class D: C300 C301 C302 C303 C304 C305 U300
component class E: C400 C401 C402 C403 C404 C405 U400
component class F: C500 C501 C502 C503 C504 C505 C506 C507 C508 D500 D501 Q500 Q501 R500 R501 R502 R503 R504 R505 R506 R507 U500 U501 U502 U503
component class G: C600 C601 C602 C603 C604 C605 C606 C607 C608 D600 D601 Q600 Q601 R600 R601 R602 R603 R604 R605 R606 R607 U600 U601 U602 U603
component class H: C700 C701 C702 C703 C704 D700 D701 D702 D703 D704 D705 D706 D707 D708 Q700 Q701 Q702 R700 R701 R702 R703 R704 R705 R706 R707 R708 R709 R710 R713 R718 R719 R720 R721 R722 R723
component class I: C800 C801 C802 C803 C804 D800 D801 D802 D803 D804 D805 D806 D807 D808 Q800 Q801 Q802 R800 R801 R802 R803 R804 R805 R806 R807 R808 R809 R810 R813 R818 R819 R820 R821 R822 R823
component class RD237_TOP_VERB: C1 CN1 D1 P1 P2 P4 P5 P7 P11 P12 TP2 TP3 TP4 TP5 TP6 TP7 TP8 TP9 TP10 TP11 TP13 TP14 TP15 TP16 TP17 TP18 TP19 TP20 TP21

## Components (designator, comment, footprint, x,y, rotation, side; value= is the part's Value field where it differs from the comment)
C1 "1 μ" 1608 82.3,27.7 r270 bottom
C2 "0.47 μ" 1608 35.675,32.8 r270 bottom
C3 "0.47 μ" 1608 41.5,33.8 r270 bottom
C4 "0.33 μ" 1608 50.5,32.6 r90 bottom
C5 "470 p" 1608 53.175,32.6 r180 top
C6 "1000 p" 1608 52.5,31.925 r0 bottom
C7 "1 μ" 1608 70.7,30.5 r0 top
C8 "0.1 μ" 1608 70.7,29.1 r0 top
C9 "100 p" 1608 64.45,28.3 r0 top
C10 "100 p" 1608 64.45,29.6 r0 top
C11 "100 p" 1608 73.7,26.9 r180 top
C12 "100 p" 1608 73.7,28.2 r180 top
C13 "0.33 μ" 1608 48.3,27.85 r90 bottom
C14 "470 p" 1608 53.2,30.225 r180 bottom
C15 "1000 p" 1608 44.15,27.8 r90 bottom
C16 "0.47 μ" 1608 36.55,29.5 r90 top
C17 "0.47 μ" 1608 42.3,29 r90 top
C18 "1000 p" 1608 58.3,34.7 r0 top
C19 "1000 p" 1608 39.3,30.45 r0 bottom
C100 "1 μ" 1608 62.65,30.1 r0 bottom
C101 "4.7 μ" 2012 61.3,34.05 r270 bottom
C102 "4.7 μ" 2012 63,34.05 r270 bottom
C103 "470 p" 1608 73.4,33.6 r180 top
C104 "47 p" 1608 81.2,48.25 r270 top
C105 "47 p" 1608 62.1,49.05 r270 top
C106 "10 μ" 1608 73.6,48.2 r0 top
C107 "10 μ" 1608 69.9,48.65 r0 top
C108 "10 μ" 1608 73.6,49.5 r0 top
C109 "10 μ" 1608 69.9,49.95 r0 top
C110 "10 μ" 1608 73.6,50.8 r0 top
C111 "1 μ" 1608 79.6,53.8 r180 top
C112 "4.7 μ" 1608 63.25,55.55 r90 top
C113 "4.7 μ" 1608 61.95,55.55 r90 top
C114 "470 p" 1608 62.65,28.4 r0 bottom
C200 "1 μ" 1608 32.25,33.3 r180 bottom
C201 "4.7 μ" 2012 32.9,29.4 r90 bottom
C202 "4.7 μ" 2012 31.2,29.4 r90 bottom
C203 "470 p" 1608 26.6,28.35 r0 top
C204 "47 p" 1608 18.8,13.75 r90 top
C205 "47 p" 1608 37.9,12.95 r90 top
C206 "10 μ" 1608 26.4,13.8 r180 top
C207 "10 μ" 1608 30.1,13.35 r180 top
C208 "10 μ" 1608 26.4,12.5 r180 top
C209 "10 μ" 1608 30.1,12.05 r180 top
C210 "10 μ" 1608 26.4,11.2 r180 top
C211 "1 μ" 1608 21.2,4.6 r0 top
C212 "4.7 μ" 1608 36.75,6.45 r270 top
C213 "4.7 μ" 1608 38.05,6.45 r270 top
C214 "470 p" 1608 32.25,34.7 r180 bottom
C300 "1 μ" 1608 44.5,48.6 r0 top
C301 "1 μ" 1608 52,48.4 r180 top
C302 "1 μ" 1608 48.2,48.35 r180 top
C303 "4.7 μ" 1608 44.5,49.95 r0 top
C304 "4.7 μ" 2012 52.2,49.85 r180 top
C305 "4.7 μ" 2012 48.15,49.8 r180 top
C400 "1 μ" 1608 55.5,13.4 r180 top
C401 "1 μ" 1608 48,13.6 r0 top
C402 "1 μ" 1608 51.8,13.65 r0 top
C403 "4.7 μ" 1608 55.5,12.05 r180 top
C404 "4.7 μ" 2012 47.8,12.15 r0 top
C405 "4.7 μ" 2012 51.85,12.2 r0 top
C500 "0.47 μ" 1608 60.8,51.8 r90 bottom
C501 "0.47 μ" 1608 55.1,51.5 r90 bottom
C502 "68 p" 1608 52.4,57.45 r90 bottom
C503 "1 μ" 1608 57.45,53.9 r180 bottom
C504 "1000 p" 1608 57.45,55.2 r180 bottom
C505 "1 μ" 1608 55.3,53.7 r90 top
C506 "1000 p" 1608 56.65,53.7 r90 top
C507 "1 μ" 1608 53.9,56.8 r270 top
C508 "1000 p" 1608 55.3,56.8 r270 top
C600 "0.47 μ" 1608 39.2,10.2 r270 bottom
C601 "0.47 μ" 1608 45.1,10.5 r270 bottom
C602 "68 p" 1608 47.6,4.55 r270 bottom
C603 "1 μ" 1608 42.55,8.1 r0 bottom
C604 "1000 p" 1608 42.55,6.8 r0 bottom
C605 "1 μ" 1608 44.7,8.3 r270 top
C606 "1000 p" 1608 43.35,8.3 r270 top
C607 "1 μ" 1608 46.1,5.2 r90 top
C608 "1000 p" 1608 44.7,5.2 r90 top
C700 "120 p" 1608 11.4,44.1 r180 top
C701 "10 μ" 2012 48.15,51.6 r0 top
C702 "10 μ" 1608 41.25,50.5 r180 top
C703 "0.1 μ" 1608 39.5,53.25 r90 bottom
C704 "0.1 μ" 1608 37.2,52.15 r0 bottom
C800 "120 p" 1608 11.3,17.45 r180 top
C801 "10 μ" 2012 51.85,10.4 r180 top
C802 "10 μ" 1608 58.75,11.5 r0 top
C803 "0.1 μ" 1608 60.5,8.75 r270 bottom
C804 "0.1 μ" 1608 62.8,9.85 r180 bottom
CN1 "XG4A-1431" XG4A-1431 91,31 r90 top locked
D1 "CRZ36" S-FLAT 84.05,28 r270 bottom
D2 "CEZ6V8" ESC 84.1,32.1 r270 bottom
D3 "CEZ6V8" ESC 84.8,29.55 r90 top
D4 "CEZ6V8" ESC 84.1,35.3 r270 bottom
D5 "CEZ6V8" ESC 84.8,26.6 r90 top
D6 "CEZ6V8" ESC 84.8,32.45 r270 top
D7 "CEZ6V8" ESC 84.8,35.55 r270 top
D100 "CEZ24V" ESC 70.15,32.15 r180 top
D101 "CRS10I60E" S-FLAT 74.1,32 r180 top
D102 "DFLS1100" POWERDI123 79.2,48.4 r270 top
D103 "CMS03" M-FLAT 64.5,48 r270 top
D104 "CEZ30V" ESC 73.75,50.9 r180 bottom
D105 "CEZ8V2" ESC 68.95,50.9 r180 bottom
D106 "CRH01" S-FLAT 71.15,54.5 r270 bottom
D107 "CRH01" S-FLAT 74.2,54.5 r90 bottom
D200 "CEZ24V" ESC 29.95,29.8 r0 top
D201 "CRS10I60E" S-FLAT 25.9,29.95 r0 top
D202 "DFLS1100" POWERDI123 20.8,13.6 r90 top
D203 "CMS03" M-FLAT 35.5,14 r90 top
D204 "CEZ30V" ESC 26.2,11.05 r0 bottom
D205 "CEZ8V2" ESC 31.05,11.1 r0 bottom
D206 "CRH01" S-FLAT 19.1,7.4 r0 top
D207 "CRH01" S-FLAT 18.7,9.2 r270 bottom
D500 "CEZ5V6" ESC 46.1,55.3 r180 bottom
D501 "1SS413" SOD-923 58.1,48.2 r180 top
D600 "CEZ5V6" ESC 53.9,6.7 r0 bottom
D601 "1SS413" SOD-923 41.9,13.8 r0 top
D700 "CBS10S30" CST2B 45.1,47.3 r90 bottom
D701 "CRZ10" S-FLAT 11.8,42.5 r180 top
D702 "CUS05F30" USC 11.4,40.85 r180 top
D703 "CRF03A" S-FLAT 4.7,37.55 r90 top
D704 "CRF03A" S-FLAT 4.7,42.15 r90 top
D705 "CRF03A" S-FLAT 4.7,46.75 r90 top
D706 "CRF03A" S-FLAT 4.7,51.35 r90 top
D707 "CRS04B" S-FLAT 37.9,55.3 r270 bottom
D708 "CRS04B" S-FLAT 35.8,55.3 r90 bottom
D800 "CBS10S30" CST2B 54.9,14.7 r270 bottom
D801 "CRZ10" S-FLAT 11.7,15.85 r180 top
D802 "CUS05F30" USC 11.3,14.2 r180 top
D803 "CRF03A" S-FLAT 4.75,10.65 r90 top
D804 "CRF03A" S-FLAT 4.75,15.25 r90 top
D805 "CRF03A" S-FLAT 4.75,19.85 r90 top
D806 "CRF03A" S-FLAT 4.75,24.45 r90 top
D807 "CRS04B" S-FLAT 62.1,6.7 r90 bottom
D808 "CRS04B" S-FLAT 64.2,6.7 r270 bottom
P1 "NTC1,1pin" TH_C17 90.01,60.2 r0 top
P2 "NTC2,2pin" TH_C17 86.2,60.2 r0 top
P4 "G-Hi, 4pin" TH_C17 36.67,60.2 r90 top
P5 "S-Hi/D-Lo, 5pin" TH_C17 32.86,60.2 r0 top
P7 "D-Hi, 7pin" TH_C17 9.99,60.2 r180 top
P11 "G-Lo, 11pin" TH_C17 59.52,1.8 r0 top
P12 "S-Lo, 12pin" TH_C17 63.33,1.8 r0 top
Q1 "SSM3K15AFS" SSM 56.125,31.7 r180 top
Q2 "2SC6026MFV" "SOT-723 (VESM)" 56.6,32.45 r0 bottom
Q3 "2SC6026MFV" "SOT-723 (VESM)" 41.925,28.15 r180 bottom
Q4 "SSM3K15AFS" SSM 56.05,29.55 r180 bottom
Q500 "2SC6026MFV" "SOT-723 (VESM)" 50.4,54.8 r270 bottom
Q501 "SSM3K318R" SOT-23F 42.3,56.4 r180 bottom
Q600 "2SC6026MFV" "SOT-723 (VESM)" 49.6,7.2 r90 bottom
Q601 "SSM3K318R" SOT-23F 57.7,5.6 r0 bottom
Q700 "TPC8132" SOP-8 42.2,55.6 r180 top
Q701 "SSM6K804R" TSOP6F 40.2,47.9 r90 top
Q702 "SSM6K804R" TSOP6F 36.6,47.9 r270 bottom
Q800 "TPC8132" SOP-8 57.8,6.4 r0 top
Q801 "SSM6K804R" TSOP6F 59.8,14.1 r270 top
Q802 "SSM6K804R" TSOP6F 63.4,14.1 r90 bottom
R1 "270" 1608 51,31.9 r270 top
R2 "4.7 k" 1608 57.2,35.1 r90 bottom
R3 "10 k" 1608 52.5,33.325 r180 bottom
R4 "4.7 k" 1608 80.9,31.5 r270 top
R5 "1 k" 1608 53.175,31.2 r180 top
R6 "100" 1608 73.7,29.5 r0 top
R7 "100" 1608 73.7,25.6 r0 top
R8 "47 k" 1608 54.7,32.65 r90 bottom
R9 "100" 1608 64.45,30.9 r180 top
R10 "100" 1608 64.45,27 r180 top
R11 "10 k" 1608 58.3,31.7 r270 top
R12 "4.7 k" 1608 81.4,34.4 r90 bottom
R13 "4.7 k" 1608 81.4,31.7 r90 bottom
R14 "4.7 k" 1608 75.7,26.3 r270 top
R15 "270" 1608 51.15,29.525 r90 bottom
R16 "4.7 k" 1608 41.35,30.6 r90 bottom
R17 "10 k" 1608 46.2,28.6 r0 bottom
R18 "1 k" 1608 53.2,28.825 r180 bottom
R19 "47 k" 1608 43.4,29.9 r0 bottom
R20 "0" 1608 40.5,34.5 r180 top
R21 "0" 1608 39.85,32.5 r90 top
R22 "10 k" 1608 58.25,29.35 r90 bottom
R100 "240 k" 1608 62.65,27.15 r180 bottom
R101 "22 k" 1608 65.45,27.15 r180 bottom
R102 "39" 1608 70.6,33.6 r180 top
R103 "390 k" 1608 71.9,29.2 r270 bottom
R104 "100 k" 1608 72.65,31.4 r180 bottom
R105 "16 k" 1608 72.65,32.8 r0 bottom
R106 "10 k" 1608 73.3,29.2 r90 bottom
R107 "33" 1608 80.3,45.7 r180 top
R108 "33" 1608 62.1,46.3 r270 top
R109 "3 k" 1608 70.7,47.85 r0 bottom
R110 "3 k" 1608 73.7,48.25 r0 bottom
R111 "3 k" 1608 70.05,49.5 r0 bottom
R112 "3 k" 1608 73.7,49.55 r0 bottom
R113 "560" 1608 78.2,53.8 r180 bottom
R114 "3 k" 1608 80.15,53.05 r90 bottom
R115 "240" 1608 76.1,54.55 r90 bottom
R200 "240 k" 1608 32.25,36.1 r0 bottom
R201 "22 k" 1608 28.95,36.1 r0 bottom
R202 "39" 1608 29.4,28.35 r0 top
R203 "390 k" 1608 22.5,33.8 r90 bottom
R204 "100 k" 1608 21.65,31.7 r0 bottom
R205 "16 k" 1608 21.65,30.25 r180 bottom
R206 "10 k" 1608 21.2,33.8 r270 bottom
R207 "33" 1608 19.7,16.3 r0 top
R208 "33" 1608 37.9,15.7 r90 top
R209 "3 k" 1608 29.3,14.15 r180 bottom
R210 "3 k" 1608 26.3,13.75 r180 bottom
R211 "3 k" 1608 29.95,12.5 r180 bottom
R212 "3 k" 1608 26.3,12.45 r180 bottom
R213 "560" 1608 21.3,10 r270 bottom
R214 "3 k" 1608 21.3,12.65 r270 bottom
R215 "240" 1608 22.7,8.5 r270 bottom
R500 "5.1 k" 1608 55.35,54.5 r270 bottom
R501 "5.1 k" 1608 53.2,55.4 r0 bottom
R502 "10 k" 1608 48.7,54.8 r270 bottom
R503 "470" 1608 51.1,57.45 r270 bottom
R504 "10 k" 1608 53.7,57.45 r90 bottom
R505 "47 k" 1608 58.4,49.5 r0 top
R506 "10" 1608 47.2,58 r0 bottom
R507 "10 k" 1608 45,57.4 r90 bottom
R600 "5.1 k" 1608 44.65,7.5 r90 bottom
R601 "5.1 k" 1608 46.8,6.6 r180 bottom
R602 "10 k" 1608 51.3,7.2 r90 bottom
R603 "470" 1608 48.9,4.55 r90 bottom
R604 "10 k" 1608 46.3,4.55 r270 bottom
R605 "47 k" 1608 41.6,12.5 r180 top
R606 "10" 1608 52.8,4 r180 bottom
R607 "10 k" 1608 55,4.6 r270 bottom
R700 "0" 1608 48.2,57.15 r270 top
R701 "91" 1608 43.05,46.7 r0 bottom
R702 "0" 1608 11.4,45.5 r0 top
R703 "1" 1608 43.05,48.05 r0 bottom
R704 "10" 3216 27.7,54.2 r270 top
R705 "10" 3216 31.9,54.2 r270 top
R706 "10" 3216 27.7,48.7 r90 top
R707 "10" 3216 31.9,48.7 r90 top
R708 "5.1 k" 1608 10.2,38.7 r90 top
R709 "10" 3216 36.1,54.2 r270 top
R710 "10" 3216 36.1,48.7 r90 top
R713 "0" 1608 40.1,49.4 r0 bottom
R718 "10" 1632 28.35,48.5 r270 bottom
R719 "10" 1632 32.55,48.5 r270 bottom
R720 "10" 1632 24.15,48.5 r270 bottom
R721 "10" 1632 24.2,55.6 r270 bottom
R722 "10" 1632 28.4,55.6 r270 bottom
R723 "10" 1632 32.6,55.6 r270 bottom
R800 "0" 1608 51.8,4.85 r90 top
R801 "91" 1608 56.95,15.3 r180 bottom
R802 "0" 1608 11.3,18.85 r0 top
R803 "1" 1608 56.95,13.95 r180 bottom
R804 "10" 3216 68.1,7.8 r90 top
R805 "10" 3216 63.9,7.8 r90 top
R806 "10" 3216 68.1,13.3 r270 top
R807 "10" 3216 63.9,13.3 r270 top
R808 "5.1 k" 1608 10.1,12.05 r90 top
R809 "10" 3216 72.3,7.8 r90 top
R810 "10" 3216 72.3,13.3 r270 top
R813 "0" 1608 59.9,12.6 r180 bottom
R818 "10" 1632 71.65,13.5 r90 bottom
R819 "10" 1632 67.45,13.5 r90 bottom
R820 "10" 1632 75.85,13.5 r90 bottom
R821 "10" 1632 71.6,6.4 r90 bottom
R822 "10" 1632 67.4,6.4 r90 bottom
R823 "10" 1632 75.8,6.4 r90 bottom
T100 "9-18Vin, 20 / 5Vout" 750319496 72,41 r180 top locked
T200 "9-18Vin, 20 / 5Vout" 750319496 28,21 r0 top locked
TP2 "VDD" "TEST PAD" 78.2,26.85 r0 top
TP3 "GND" "TEST PAD" 82.65,27.65 r0 top
TP4 "VE_A" "TEST PAD" 38.9,51.5 r0 top
TP5 "VEE_A" "TEST PAD" 55.1,51 r0 top
TP6 "VCC2_A" "TEST PAD" 47.6,53.8 r0 top
TP7 "C_A" "TEST PAD" 45.45,33.8 r0 top
TP8 "A_A" "TEST PAD" 48.05,33.15 r0 top
TP9 "5V_A" "TEST PAD" 42.4,32.8 r0 top
TP10 "VOUTP_A" "TEST PAD" 50.9,55.25 r270 top
TP11 "VOUTN_A" "TEST PAD" 58.45,46.35 r90 top
TP13 "VCC2_B" "TEST PAD" 52.4,8.2 r90 top
TP14 "VE_B" "TEST PAD" 61.1,10.5 r90 top
TP15 "5V_B" "TEST PAD" 47.9,29 r90 top
TP16 "VEE_B" "TEST PAD" 44.9,11 r90 top
TP17 "GND_B" "TEST PAD" 44.9,28.2 r90 top
TP18 "A_B" "TEST PAD" 53.95,29.05 r90 top
TP19 "C_B" "TEST PAD" 50.95,29.05 r90 top
TP20 "VOUTP_B" "TEST PAD" 49.1,6.75 r90 top
TP21 "VOUTN_B" "TEST PAD" 41.55,15.65 r90 top
TP100 "SWB" "TEST PAD" 78.75,34.65 r90 top
TP200 "SWC" "TEST PAD" 22.05,30.05 r0 top
U1 "TCR1HF50B" "SOT-25 (SMV)" 38.5,33.75 r0 bottom
U2 "TC7W08FK" "SOT-765 (US8)" 69.45,26.95 r0 top
U3 "TCR1HF50B" "SOT-25 (SMV)" 39.45,29.1 r0 top
U100 "LT8302IS8E" 8-SOIC 67.5,30.85 r0 bottom
U101 "LM317MKVURG3" TO-252-3 69.85,55.1 r180 top
U200 "LT8302IS8E" 8-SOIC 26.8,32.5 r180 bottom
U201 "LM317MKVURG3" TO-252-3 30.15,6.9 r0 top
U300 "TLP5231" SO16L 50,41 r90 top locked
U400 "TLP5231" SO16L 50,21 r270 top locked
U500 "TCR1HF50B" "SOT-25 (SMV)" 58,51.3 r180 bottom
U501 "TC75S57FU" USV 56.2,57.2 r0 bottom
U502 "TC7W00FK" "SOT-765 (US8)" 58.6,52.75 r90 top
U503 "TC7SZ04AFS" "SOT-953 (FSV)" 57.025,56.25 r180 top
U600 "TCR1HF50B" "SOT-25 (SMV)" 42,10.7 r0 bottom
U601 "TC75S57FU" USV 43.8,4.8 r180 bottom
U602 "TC7W00FK" "SOT-765 (US8)" 41.4,9.25 r270 top
U603 "TC7SZ04AFS" "SOT-953 (FSV)" 42.975,5.75 r0 top
? "Comment" FD 87.9,67 r0 top
? "Comment" FD 87.9,67 r180 bottom
? "Comment" FD 87.9,-5 r0 top
? "Comment" FD 87.9,-5 r180 bottom
? "Comment" FD 12.2,-5 r180 bottom
? "Comment" FD 12.2,-5 r0 top

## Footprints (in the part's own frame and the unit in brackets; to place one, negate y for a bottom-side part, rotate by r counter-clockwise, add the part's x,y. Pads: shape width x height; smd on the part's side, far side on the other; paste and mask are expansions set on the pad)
8-SOIC [mm]
  rect 1.143x0.76 smd mask+0.05: 1(-2.601,1.905) 3(-2.601,-0.635) 4(-2.601,-1.905) 5(2.601,-1.905) 6(2.601,-0.635) 7(2.601,0.635) 8(2.601,1.905)
  rect 1.143x0.76 smd paste+0 mask+0.05: 2(-2.601,0.635)
  rect 2.26x2.99 smd paste-10 mask+0.05: 9(0,0)
  silkscreen extent -3.49,-2.66 3.49,2.66, body extent -2.97,-2.45 3.02,2.46, height 1.75
1608 [mm]
  rect 0.7x0.8 smd mask+0.05: 1(-0.75,0) 2(0.75,0)
  silkscreen extent -1.33,-0.63 1.33,0.63, body extent -0.8,-0.4 0.8,0.4, height 0.9
1632 [mm]
  rect 1.1x3.7 smd mask+0.05: 1(-0.95,0) 2(0.95,0)
  silkscreen extent -1.88,-2.23 1.88,2.23, body extent -0.8,-1.6 0.8,1.6, height 0.6
2012 [mm]
  rect 0.7x1.1 smd mask+0.05: 1(-0.95,0) 2(0.95,0)
  silkscreen extent -1.53,-0.77 1.53,0.77, body extent -1,-0.63 1,0.63, height 1.45
3216 [mm]
  rect 1.1x3.7 smd mask+0.05: 1(-0.95,0) 2(0.95,0)
  silkscreen extent -1.88,-2.23 1.88,2.23, body extent -0.8,-1.6 0.8,1.6, height 0.6
750319496 [mm] "Auxiliary Gate Drive Transformer, EP7 SMT, body 11.3x10.95mm"
  rect 1.17x1.54 smd paste+0.165 mask+0.05: 1(-3.75,4.82) 2(-1.25,4.82) 3(1.25,4.82) 4(3.75,4.82) 5(3.75,-4.82) 6(1.25,-4.82) 7(-1.25,-4.82) 8(-3.75,-4.82)
  silkscreen extent -5.65,-5.48 5.65,6.22, body extent -5.55,-5.05 5.55,5.05, height 11.56
CST2B [mm]
  rect 0.65x0.7 smd mask+0.05: 1(-0.325,0)
  rect 0.25x0.7 smd mask+0.05: 2(0.325,0)
  silkscreen extent -1.27,-0.73 0.83,0.73, body extent -0.7,-0.4 0.5,0.4, height 0.38
ESC [mm]
  rect 0.6x0.8 smd mask+0.05: 1(-0.85,0) 2(0.85,0)
  silkscreen extent -1.78,-0.78 1.53,0.78, body extent -0.8,-0.4 0.8,0.4, height 0.6
FD [mm]
  round 1 smd mask+1: 1(0,0)
  Keep-Out Layer circle w0.05: c0,0 r1.6
M-FLAT [mm]
  rect 1.4x2.1 smd mask+0.05: 1(-2.2,0) 2(2.2,0)
  silkscreen extent -3.28,-1.43 3.56,1.43, body extent -2.35,-1.2 2.35,1.2, height 1.03
POWERDI123 [mm]
  rect 2.4x1.5 smd mask+0.05: 1(-1.187,0)
  rect 1.05x1.5 smd mask+0.05: 2(1.188,0)
  silkscreen extent -3.05,-1.13 2.09,1.13, body extent -2.19,-0.88 1.51,0.89, height 0.98
S-FLAT [mm]
  rect 1.2x1.2 smd mask+0.05: 1(-1.4,0) 2(1.4,0)
  silkscreen extent -2.38,-0.98 2.67,0.98, body extent -1.75,-0.8 1.75,0.8, height 1.03
SO16L [mm]
  rect 1.3x0.8 smd mask+0.05: 1(-4.75,4.445) 2(-4.75,3.175) 3(-4.75,1.905) 4(-4.75,0.635) 5(-4.75,-0.635) 6(-4.75,-1.905) 7(-4.75,-3.175) 8(-4.75,-4.445) 9(4.75,-4.445) 10(4.75,-3.175) 12(4.75,-0.635) 13(4.75,0.635) 14(4.75,1.905) 15(4.75,3.175) 16(4.75,4.445)
  rect 1.3x0.8 smd paste+0 mask+0.05: 11(4.75,-1.905)
  silkscreen extent -6.35,-5.45 5.78,5.45, body extent -5,-5.15 5,5.15, height 2.3
SOD-923 [mm]
  rect 0.325x0.4 smd mask+0.05: 1(-0.437,0) 2(0.437,0)
  silkscreen extent -1.27,-0.58 0.98,0.58, body extent -0.5,-0.3 0.5,0.3, height 0.4
SOP-8 [mm]
  rect 1x0.5 smd mask+0.05: 1(-2.75,1.905) 2(-2.75,0.635) 3(-2.75,-0.635) 4(-2.75,-1.905) 5(2.75,-1.905) 6(2.75,-0.635) 7(2.75,0.635) 8(2.75,1.905)
  silkscreen extent -4,-2.75 3.63,2.75, body extent -3,-2.45 3,2.45, height 1.67
SOT-23F [mm]
  rect 0.9x0.8 smd mask+0.05: 1(-1.05,0.95) 2(-1.05,-0.95) 3(1.05,0)
  silkscreen extent -1.88,-1.73 1.88,1.73, body extent -1.2,-1.45 1.2,1.45, height 0.8
"SOT-25 (SMV)" [mm]
  rect 1x0.8 smd mask+0.05: 1(-1.2,0.95) 3(-1.2,-0.95) 4(1.2,-0.95)
  rect 1x0.6 smd mask+0.05: 2(-1.2,0)
  rect 1x0.8 smd paste+0 mask+0.05: 5(1.2,0.95)
  silkscreen extent -2.08,-1.73 2.08,1.73, body extent -1.4,-1.45 1.4,1.45, height 1.15
"SOT-723 (VESM)" [mm]
  rect 0.45x0.4 smd mask+0.05: 1(-0.575,0.4) 2(-0.575,-0.4)
  rect 0.45x0.5 smd mask+0.05: 3(0.575,0)
  silkscreen extent -1.18,-0.98 1.18,0.98, body extent -0.6,-0.6 0.6,0.6, height 0.5
"SOT-765 (US8)" [mm]
  rect 0.7x0.3 smd mask+0.05: 1(-1.35,0.75) 2(-1.35,0.25) 3(-1.35,-0.25) 4(-1.35,-0.75) 5(1.35,-0.75) 6(1.35,-0.25) 7(1.35,0.25) 8(1.35,0.75)
  silkscreen extent -2.08,-1.28 2.08,1.28, body extent -1.55,-1 1.55,1, height 0.75
"SOT-953 (FSV)" [mm]
  rect 0.2x0.2 smd mask+0.025: 1(-0.425,0.35) 2(-0.425,0)
  rect 0.2x0.2 smd mask+0.05: 3(-0.425,-0.35) 4(0.425,-0.35) 5(0.425,0.35)
  silkscreen extent -0.88,-0.88 0.88,0.88, body extent -0.5,-0.5 0.5,0.5, height 0.48
SSM [mm]
  rect 0.6x0.6 smd mask+0.05: 1(-0.7,0.5) 2(-0.7,-0.5) 3(0.7,0)
  silkscreen extent -1.38,-1.18 1.38,1.18, body extent -0.8,-0.8 0.8,0.8, height 0.75
"TEST PAD" [mm]
  round 2 smd paste-2539.97 mask+0.05: 1(0,0)
  silkscreen extent -1.2,-1.2 1.2,1.2
TH_C17 [mm]
  round 2.2 hole 1.7 mask+0.05: 1(0,0)
  silkscreen extent -1.37,-1.37 1.37,1.37
TO-252-3 [mm]
  rect 2.75x1 smd mask+0.05: 1(-4.2,2.29)
  rect 2.75x1 smd paste+0 mask+0.05: 3(-4.2,-2.29)
  rect 6.15x5.55 smd mask+0.05: 4(2.5,0)
  silkscreen extent -5.95,-3.56 5.95,3.56, body extent -5.22,-3.26 5.23,3.26, height 2.31
TSOP6F [mm]
  rect 0.7x0.62 smd mask+0.05: 1(-1.25,0.95) 2(-1.25,0) 3(-1.25,-0.95) 4(1.25,-0.95) 5(1.25,0) 6(1.25,0.95)
  silkscreen extent -1.98,-1.64 1.98,1.64, body extent -1.4,-1.45 1.4,1.45, height 0.81
USC [mm]
  rect 0.8x0.9 smd mask+0.05: 1(-1.15,0) 2(1.15,0)
  silkscreen extent -1.93,-0.83 2.18,0.83, body extent -1.25,-0.63 1.25,0.63, height 0.9
USV [mm]
  rect 0.8x0.4 smd mask+0.05: 1(-0.95,0.65) 2(-0.95,0) 3(-0.95,-0.65) 4(0.95,-0.65) 5(0.95,0.65)
  silkscreen extent -1.73,-1.23 1.73,1.23, body extent -1.05,-1 1.05,1, height 0.95
XG4A-1431 [mm]
  round 1.3 hole 0.8 mask+0.05: 1(-7.62,-1.27) 2(-7.62,1.27) 3(-5.08,-1.27) 4(-5.08,1.27) 5(-2.54,-1.27) 6(-2.54,1.27) 7(0,-1.27) 8(0,1.27) 9(2.54,-1.27) 10(2.54,1.27) 11(5.08,-1.27) 12(5.08,1.27) 13(7.62,-1.27) 14(7.62,1.27)
  round 3.2 hole 3.2 unplated mask+0.05: M1(-16.5,0.27) M2(16.5,0.27)
  silkscreen extent -18.67,-5.17 18.67,4.27, body extent -18.55,-4.4 18.55,4.1, height 26.26

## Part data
C1 C111 C211 C300 C301 C302 C400 C401 C402: library part 1u/50V/1608, "Ceramic, 50V, ±10 %, X7R", Manufacturer="Taiyo Yuden", Part Number=UMK107AB7105KA-T
C2 C3 C16 C17: library part 470n/50V/1608, "Ceramic, 50V, ±10 %, X7R", Manufacturer="Taiyo Yuden", Part Number=UMK107B7474KA-TR
C4 C13: library part 330n/16V/1608, "Ceramic, 16V, ±10 %, X7R", Manufacturer=KEMET, Part Number=C0603C334K4RAC7867
C5 C14 C103 C114 C203 C214: library part 470p/50V/1608, "Ceramic, 50V, ±10 %, X7R", Manufacturer=KEMET, Part Number=C0603C471K5RAC7867
C6 C15 C18 C19 C504 C506 C508 C604 C606 C608: library part 1000p/50V/1608, "Ceramic, 50V, ±10 %, X7R", Manufacturer="Murata Electronics", Part Number=GCM188R71H102KA37D
C7 C100 C200 C503 C505 C507 C603 C605 C607: library part 1u/25V/1608, "Ceramic, 25V, ±10 %, X7R", Manufacturer=KEMET, Part Number=C0603C105K3RAC7411
C8 C703 C704 C803 C804: library part 100n/50V/1608_GCM, "Ceramic, 50V, ±10 %, X7R", Manufacturer="Murata Electronics", Part Number=GCM188R71H104KA57D
C9 C10 C11 C12: library part 100p/50V/1608, "Ceramic, 50V, ±10 %, X7R", Manufacturer=KEMET, Part Number=C0603C101K5RAC7867
C101 C102 C201 C202 C304 C305 C404 C405: library part 4u7/50V/2012, "Ceramic, 50V, ±10 %, X7R", Manufacturer="Murata Electronics", Part Number=GRM21BZ71H475KE15K
C104 C105 C204 C205: library part 47p/100V/1608, "Ceramic, 100V, ±10 %, X7R", Manufacturer=KEMET, Part Number=C0603C470K1RAC7867
C106 C107 C108 C109 C110 C206 C207 C208 C209 C210 C702 C802: library part 10u/35V/1608, "Ceramic, 35V, ±20 %, X5R", Manufacturer="Murata Electronics", Part Number=GRM188R6YA106MA73D
C112 C113 C212 C213: library part 4u7/35V/1608, "Ceramic, 35V, ±10 %, X5R", Manufacturer="Murata Electronics", Part Number=GRM188R6YA475KE15D
C303 C403: library part 4u7/16V/1608, "Ceramic, 16V, ±10 %, X7R", Manufacturer="Murata Electronics", Part Number=GRM188Z71C475KE21D
C500 C501 C600 C601: library part 470n/25V/1608, "Ceramic, 25V, ±10 %, X7R", Manufacturer=KEMET, Part Number=C0603C474K3RAC7867
C502 C602: library part 68p/25V, "Ceramic, 25V, ±10 %, X7R", Manufacturer=KEMET, Part Number=C0603C680K5RACAUTO
C700 C800: library part 120p/50V/1608, "Ceramic, 50V, ±10 %, X7R", Manufacturer=KEMET, Part Number=C0603C121K5RAC7867
C701 C801: library part 10u/50V/2012, "Ceramic, 50V, ±10 %, X5R", Part Number=GRM21BR61H106KE43L
CN1: library part "XG4A-1431, 14PIN, 2列", "CONNECTOR", Manufacturer=OMRON
D1 D2 D3 D4 D5 D6 D7 D100 D104 D105 D200 D204 D205 D500 D600 D701 D801: "Zener Diode", Manufacturer=toshiba
D101 D103 D201 D203 D501 D601 D700 D702 D707 D708 D800 D802 D807 D808: "SBD", Manufacturer=toshiba
D102 D202: "SBD", Manufacturer="Diodes Incorporated"
D106 D107 D206 D207: "Rectifier Diode", Manufacturer=toshiba
D703 D704 D705 D706 D803 D804 D805 D806: "Fast Recovery Diode", Manufacturer=toshiba
P1 P2 P4 P5 P7 P11 P12: library part "through hole_Φ1.7", "through hole", Part Number=Φ1.7mm
Q1 Q4 Q501 Q601 Q701 Q702 Q801 Q802: "Nch-MOSFET", Manufacturer=toshiba
Q2 Q3 Q500 Q600: "NPN biporar", Manufacturer=toshiba
Q700 Q800: "Pch-MOSFET", Manufacturer=toshiba
R1 R15: library part 270/1%/0.125W/1608, "Resistor", Manufacturer="KOA Speer Electronics, Inc.", Part Number=RK73H1JTTD2700F
R2 R4 R12 R13 R14 R16: library part 4K7, "Resistor RK73H1J series", Manufacturer="KOA Speer Electronics, Inc.", Part Number=RK73H1JTTD4701F
R3 R11 R17 R22 R502 R504 R507 R602 R604 R607: library part 10K/1%_RK73, "Resistor RK73H1J series", Manufacturer="KOA Speer Electronics, Inc.", Part Number=RK73H1JTTD1002F
R5 R18: library part 1K/1%/0.125W, "Resistor RK73H series", Manufacturer="KOA Speer Electronics, Inc.", Part Number=RK73H1JTTD1001F
R6 R7 R9 R10: library part 100R, "Resistor", Manufacturer="KOA Speer Electronics, Inc.", Part Number=RK73H1JTTDD1000F
R8 R19 R505 R605: library part 47K_RK73, "Resistor RK73H series", Manufacturer="KOA Speer Electronics, Inc.", Part Number=RK73H1JTTD4702F
R20 R21 R700 R702 R713 R800 R802 R813: "Resistor", Manufacturer="KOA Speer Electronics, Inc.", Part Number=RK73Z1JTTD
R100 R200: library part 240K, "Resistor", Manufacturer="KOA Speer Electronics, Inc.", Part Number=RK73H1JTTD2403F
R101 R201: library part 22K, "Resistor", Manufacturer="KOA Speer Electronics, Inc.", Part Number=RK73H1JTTD2202F
R102 R202: library part 39/1%/0.125W, "Resistor RK73H series", Manufacturer="KOA Speer Electronics, Inc.", Part Number=RK73H1JTTD39R0F
R103 R203: library part 390K/0.1%, "Resistor", Manufacturer="KOA Speer Electronics, Inc.", Part Number=RK73H1JTTD3903F
R104 R204: library part 100K/1%/0.1W/1608, "Resistor", Manufacturer="KOA Speer Electronics, Inc.", Part Number=RK73H1JTTD1003F
R105 R205: library part 16K/1%/0.1W/1608, "Resistor", Manufacturer="KOA Speer Electronics, Inc.", Part Number=RK73H1JTTD1602F
R106 R206: library part 10K/1%/0.1W/1608, "Resistor RK73H1J series", Manufacturer="KOA Speer Electronics, Inc.", Part Number=RK73H1JTTD1002F
R107 R108 R207 R208: library part 33/1%_RK73H, "Resistor RK73B series", Manufacturer="KOA Speer Electronics, Inc.", Part Number=RK73H1JTTD33R0F
R109 R110 R111 R112 R209 R210 R211 R212: library part 3K/0.3W/1608, "Resistor", Manufacturer="KOA Speer Electronics, Inc.", Part Number=SG73P1JTTD3001F
R113 R213: library part 560/1%/0.125W/1608, "Resistor", Manufacturer="KOA Speer Electronics, Inc.", Part Number=RK73H1JTTD5600F
R114 R214: library part 3K/1%/0.1W/1608, "Resistor", Manufacturer="KOA Speer Electronics, Inc.", Part Number=RK73H1JTTD3001F
R115 R215: library part 240/1%/0.125W/1608, "Resistor", Manufacturer="KOA Speer Electronics, Inc.", Part Number=RK73H1JTTD2400F
R500 R501 R600 R601 R708 R808: library part 5K1/1%/0.1W/1608, "Resistor", Manufacturer="KOA Speer Electronics, Inc.", Part Number=RK73H1JTTD5101F
R503 R603: library part 470/1%/0.125W/1608, "Resistor", Manufacturer="KOA Speer Electronics, Inc.", Part Number=RK73H1JTTD4700F
R506 R606: library part 10/1%/0.125W/1608, "Resistor", Manufacturer="KOA Speer Electronics, Inc.", Part Number=RK73H1JTTD10R0F
R701 R801: library part 91R/1%/0.125W/1608, "Resistor", Manufacturer="KOA Speer Electronics, Inc.", Part Number=RK73H1JTTD91R0F
R703 R803: "Resistor", Manufacturer="KOA Speer Electronics, Inc.", Part Number=SG73P1JTTD1R00F
R704 R705 R706 R707 R709 R710 R718 R719 R720 R721 R722 R723 R804 R805 R806 R807 R809 R810 R818 R819 R820 R821 R822 R823: library part 10/1632/1W, "Resistor", Manufacturer=SUSUMU, Part Number=PRG3216P-10R0-D-T5
T100 T200: library part 750319496, "WE-AGDT SMT Auxiliary Gate Drive Transformer, EP7, 9-18Vin, 20 / 5Vout, 7.3pF", Case/Size Code=EP7, Inductance=7uH, Input Voltage=9-18V, Interwinding Capacitance=7.3pF, Manufacturer="Wurth Elektronik", Operating Temperature Max=130°C, Operating Temperature Min=-40°C, Output Power=6W, Output Voltage=20V, Output Voltage 2=5V, Saturation Current=4.5A, Switching Frequency=350kHz
TP2 TP3 TP4 TP5 TP6 TP7 TP8 TP9 TP10 TP11 TP13 TP14 TP15 TP16 TP17 TP18 TP19 TP20 TP21 TP100 TP200: library part "TEST PAD", "PAD"
U1 U3 U500 U600: "LDO", Manufacturer=toshiba
U2: "2 AND logic", Manufacturer=toshiba
U100 U200: "42VIN UP NO-OPTO ISO FLY CONV", Manufacturer="analog devices", Part Number=LT8302IS8E#WTRPBF
U101 U201: "LDO", Manufacturer="Texas Instruments"
U300 U400: "Gate-Driver", Manufacturer=toshiba
U501 U601: "Comprator", Manufacturer=toshiba
U502 U602: "2 NAND logic", Manufacturer=toshiba
U503 U603: "INV", Manufacturer=toshiba

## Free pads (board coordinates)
  round 2.8 hole 2.8 unplated mask+0.5: NTH1(2.75,2.25) NTH2(2.75,59.75) NTH3(97.25,2.25) NTH4(97.25,59.75)
  round 4 hole 4 unplated mask+0.5: NTH3(5,-5) NTH3(5,67) NTH3(95,-5) NTH3(95,67)

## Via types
v1: diameter 0.8, hole 0.4, Top Layer to Bottom Layer, 304 vias

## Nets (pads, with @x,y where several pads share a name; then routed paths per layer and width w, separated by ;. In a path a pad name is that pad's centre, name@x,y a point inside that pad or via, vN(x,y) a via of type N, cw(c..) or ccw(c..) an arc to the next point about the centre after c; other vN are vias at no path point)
5V_A: C3.2 C4.2 C7.2 C8.2 R1.2 R2.2 R3.2 R4.1 R12.1 R20.1 TP9.1 U1.5 U2.8 U300.6 | length 63.9
  Top Layer w0.3: v1(43.9,32.3) 43.9,32.25 44.05,32.1 46.75,32.1 47.35,31.5 48.2,31.5 49,30.7 50.55,30.7 R1.2@51,31.15 ; U2.8@70.8,27.7 71.45,28.35 C8.2@71.45,29.1 C7.2@71.45,30.5 71.5,30.55 78.15,30.55 79.6,32 79.6,32.8 v1(80.1,33.3) 80.6,33.3 80.9,33 R4.1@80.9,32.25
  Top Layer w0.5: v1(51.905,34.705) U300.6@51.905,36.25
  POWER 3 w0.3: v1(51.905,34.705) 51.905,34.245 53.05,33.1 73.75,33.1 76.05,30.8 78.5,30.8 80.1,32.4 v1(80.1,33.3)
  Bottom Layer w0.3: 55.85,35.85 R2.2@57.2,35.85
  Bottom Layer w0.5: 49.35,33.35 C4.2@50.5,33.35 51.725,33.35 R3.2@51.75,33.325 51.905,33.48 v1(51.905,34.705) 51.905,35.795 ; v1(80.1,33.3) 80.45,33.65 R12.1@81.4,33.65
5V_B: C13.2 C17.2 R15.2 R16.2 R17.2 R21.1 TP15.1 U3.5 U400.6 | length 11.1
  Top Layer w0.3: R21.1@39.85,31.75 40.75,30.85
  Top Layer w0.5: U400.6@48.095,25.75 48.095,27.295
  Bottom Layer w0.3: R16.2@41.35,31.35 42.15,31.35 42.55,30.95 45,30.95 v1(45.45,30.5) ; 46.95,29.85 R17.2@46.95,28.6 C13.2@48.3,28.6 ; 49.875,30.275 R15.2@51.15,30.275
A_ENA: CN1.9 D4.1 R10.2 R12.2 | length 43.6
  Top Layer w0.3: v1(60.4,27.05) R10.2@63.7,27.05
  Bottom Layer w0.3: v1@60.384,27.011 60.384,26.416 60.75,26.05 74.6,26.05 77.75,29.2 77.75,30.2 79.05,31.5 79.05,34.6 79.6,35.15 R12.2@81.4,35.15 82.05,35.15 83.05,36.15 D4.1@84.1,36.15 86,36.15 87.35,34.8 91.01,34.8 CN1.9@92.27,33.54
A_FLT: C18.2 CN1.12 D7.1 Q2.3 R2.1 | length 37.9
  Top Layer w0.3: C18.2@59.05,34.7 v1(59.05,35.8) ; v1(81.7,36.4) D7.1@84.8,36.4 86.4,36.4 86.72,36.08 CN1.12@89.73,36.08
  POWER 3 w0.3: v1(59.05,35.8) 60.15,34.7 78.8,34.7 79.4,35.3 80.6,35.3 v1(81.7,36.4)
  Bottom Layer w0.3: Q2.3@57.175,32.45 57.175,34.325 R2.1@57.2,34.35 58.35,34.35 59.05,35.05 v1(59.05,35.8)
